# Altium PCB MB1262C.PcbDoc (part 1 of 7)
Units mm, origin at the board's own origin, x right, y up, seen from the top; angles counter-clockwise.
Board outline 208 x 250 mm, 6 copper layers (Top Layer, Layer 2, Layer 3, Layer 4, Layer 5, Bottom Layer), stack 1.596 mm thick; 483 components, 502 nets, 2134 pads, 1709 vias.
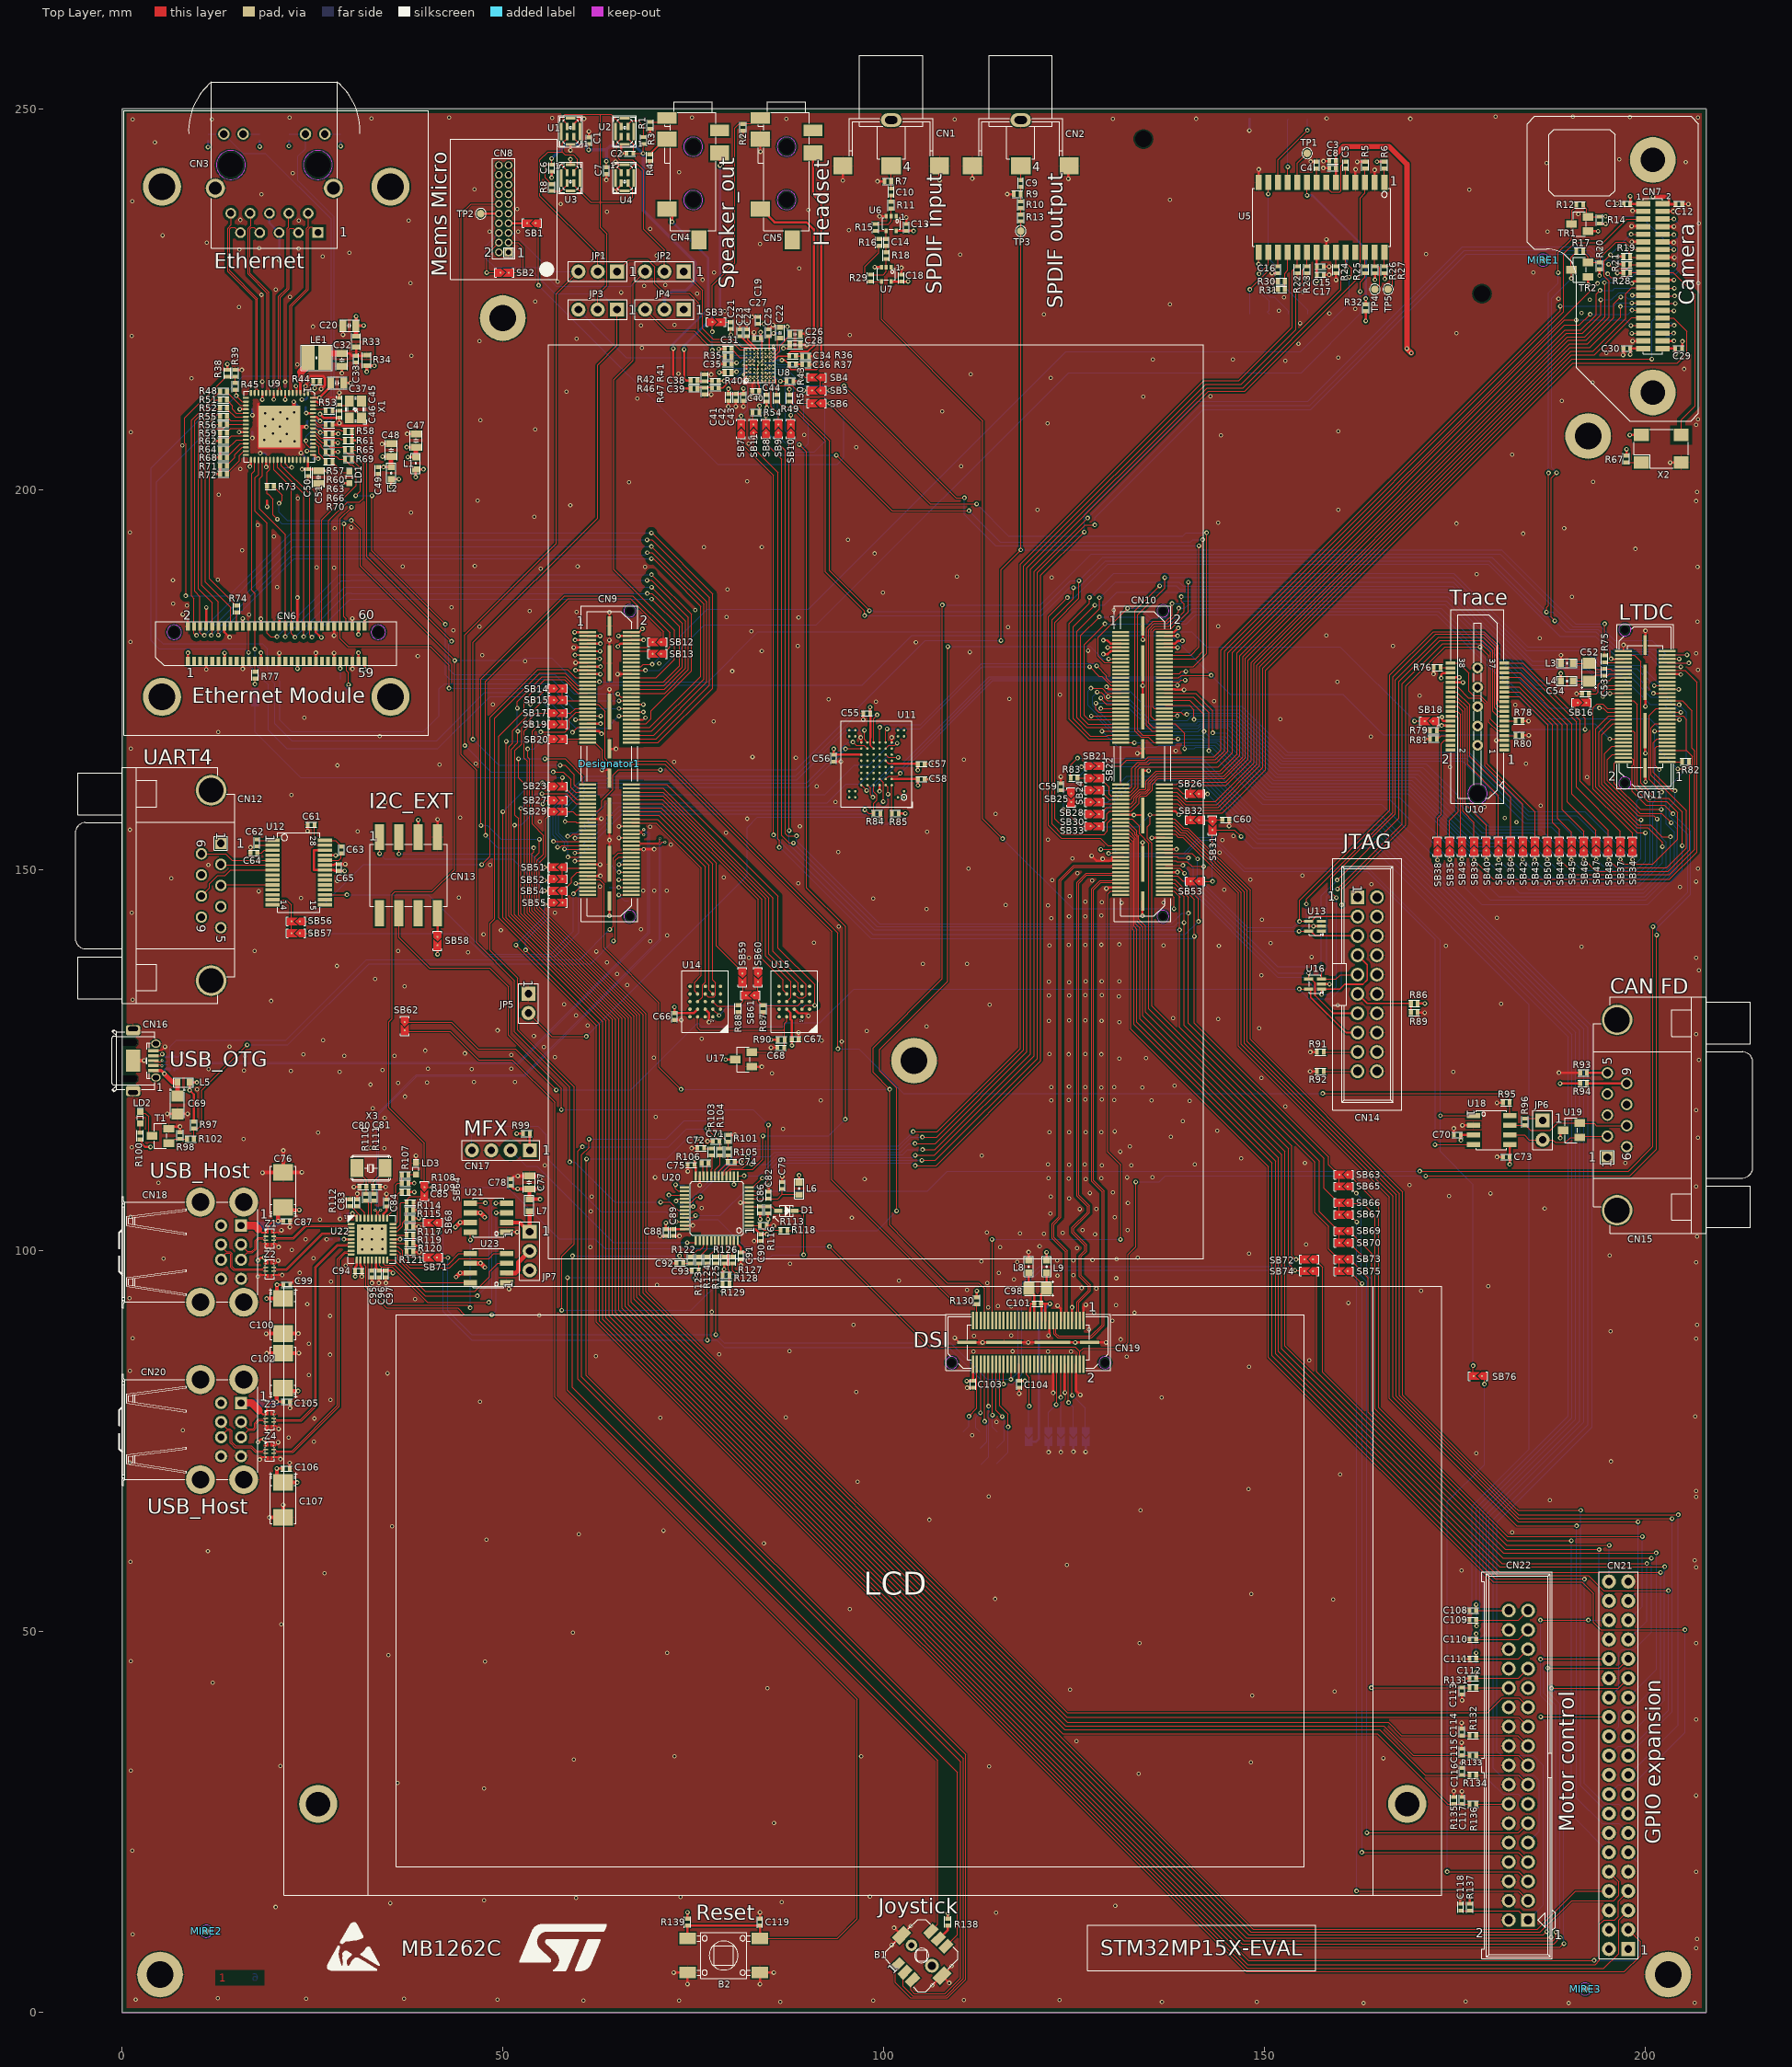
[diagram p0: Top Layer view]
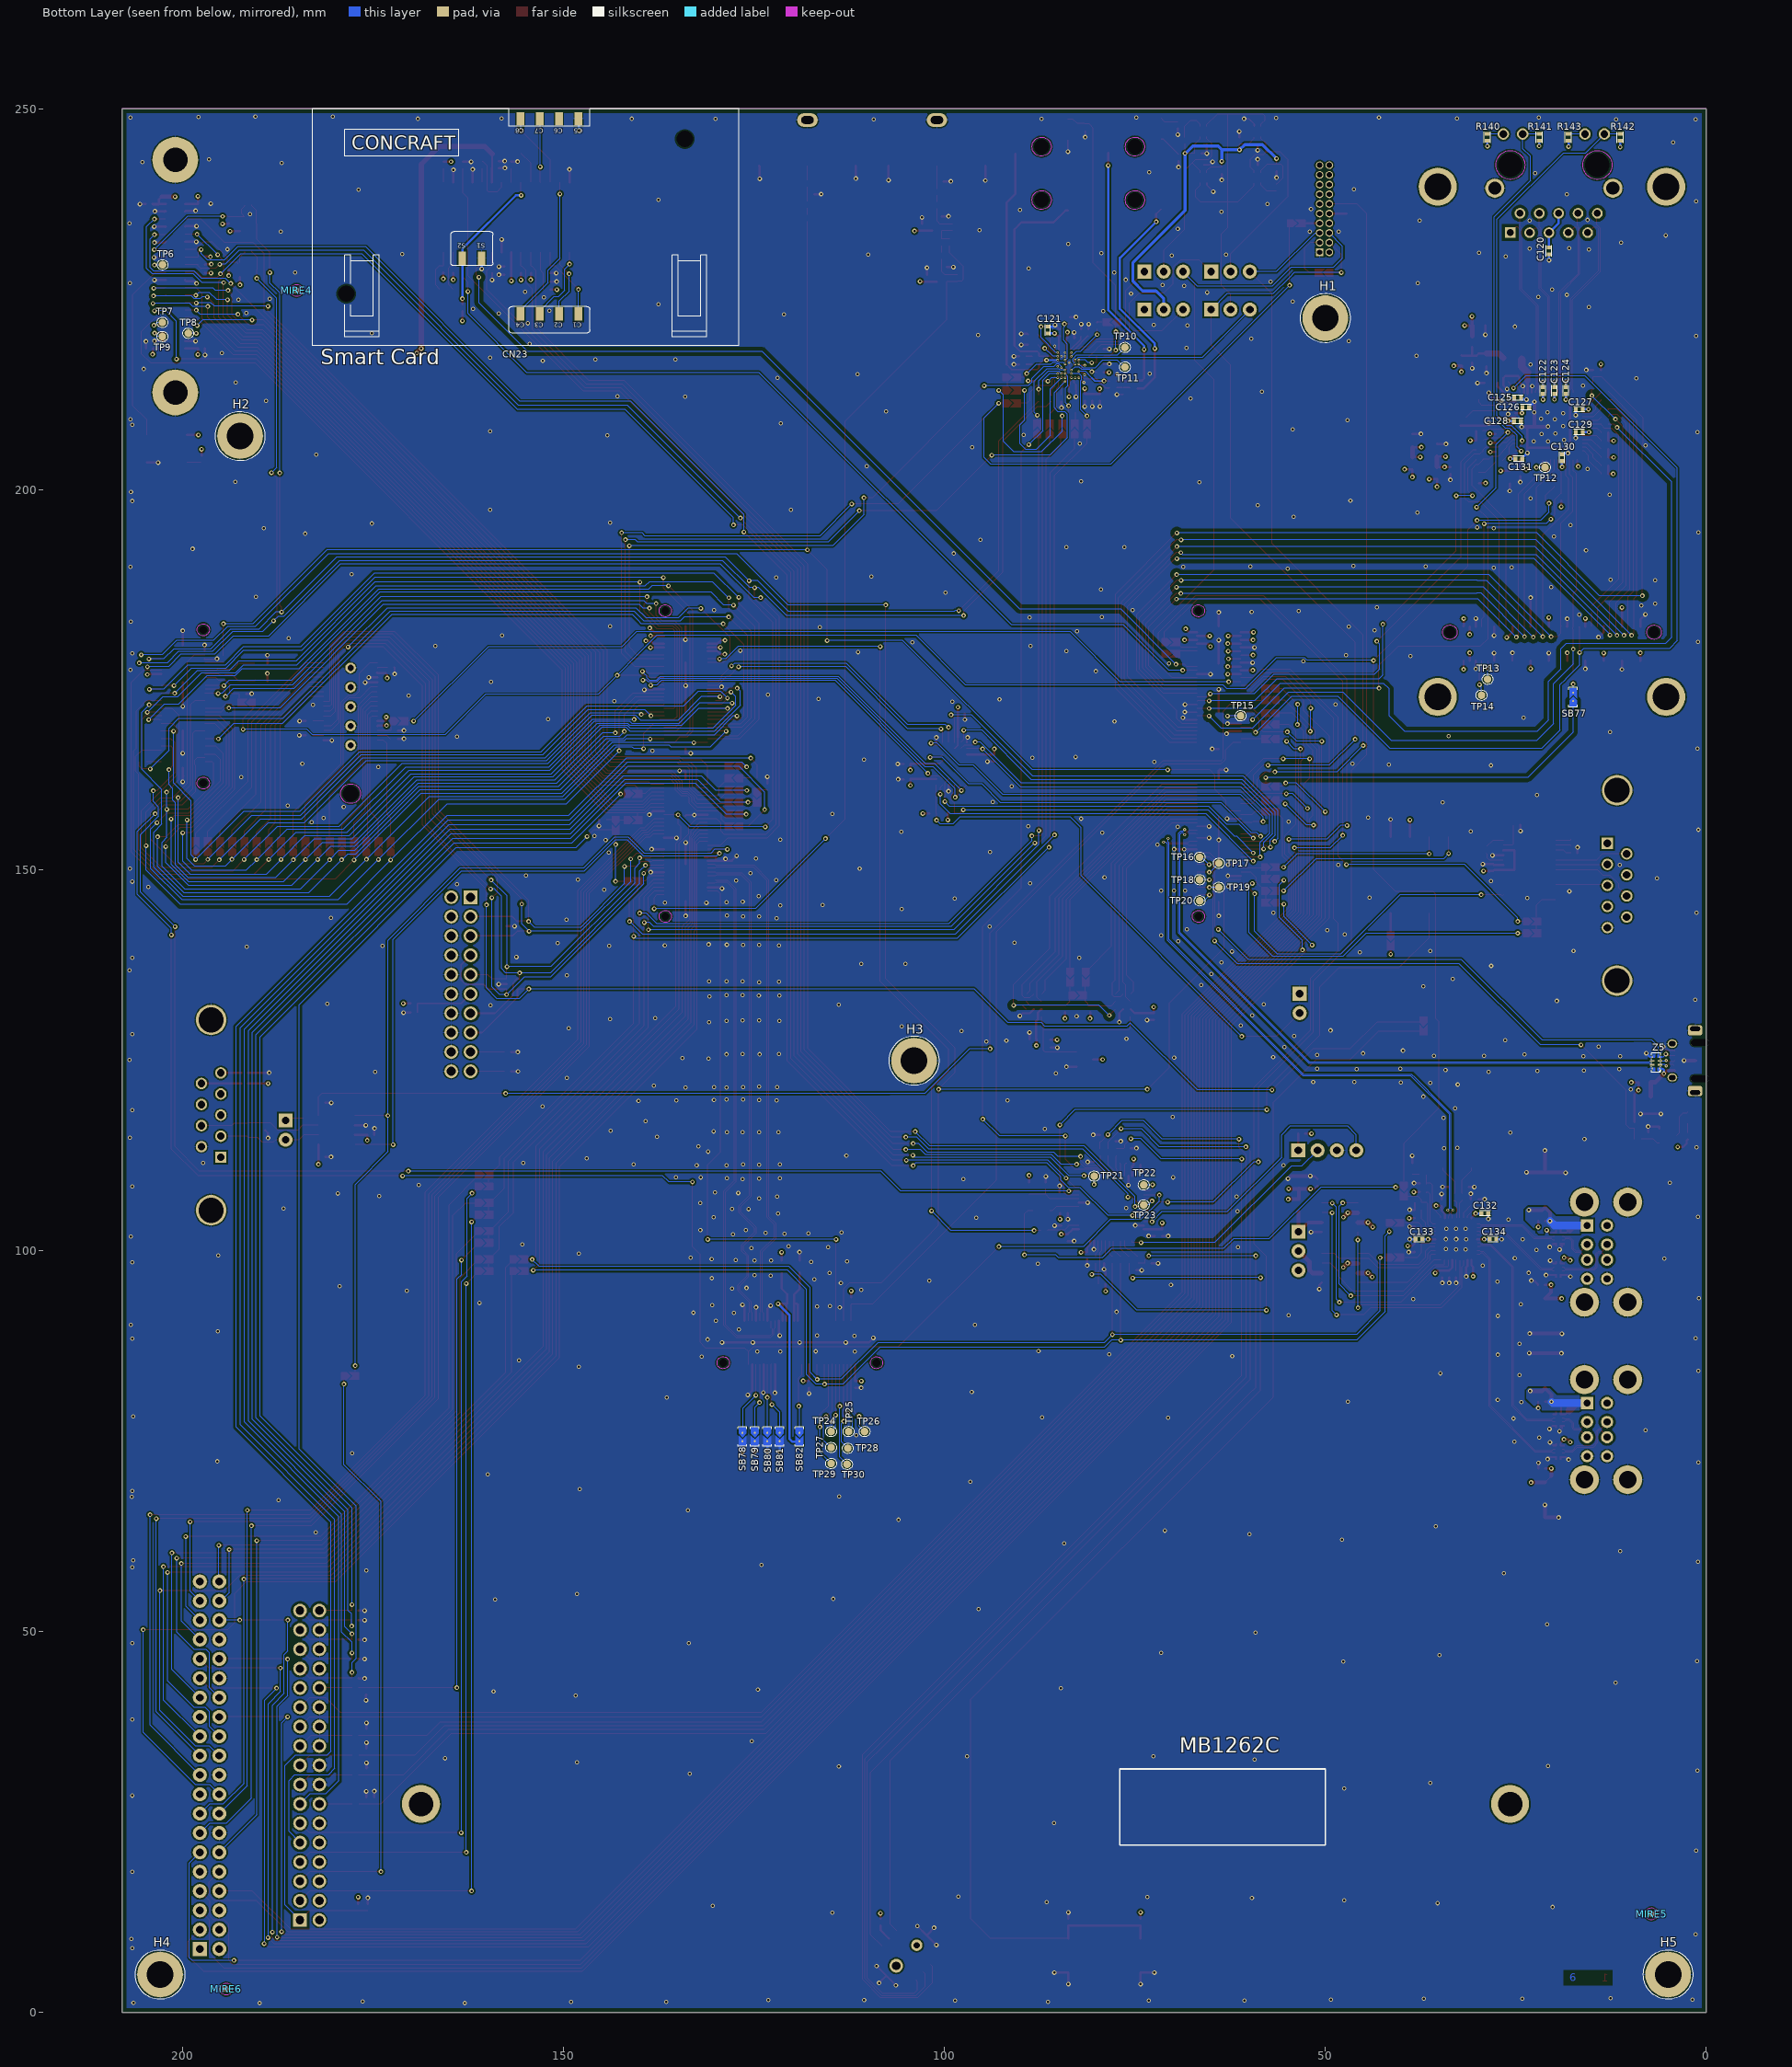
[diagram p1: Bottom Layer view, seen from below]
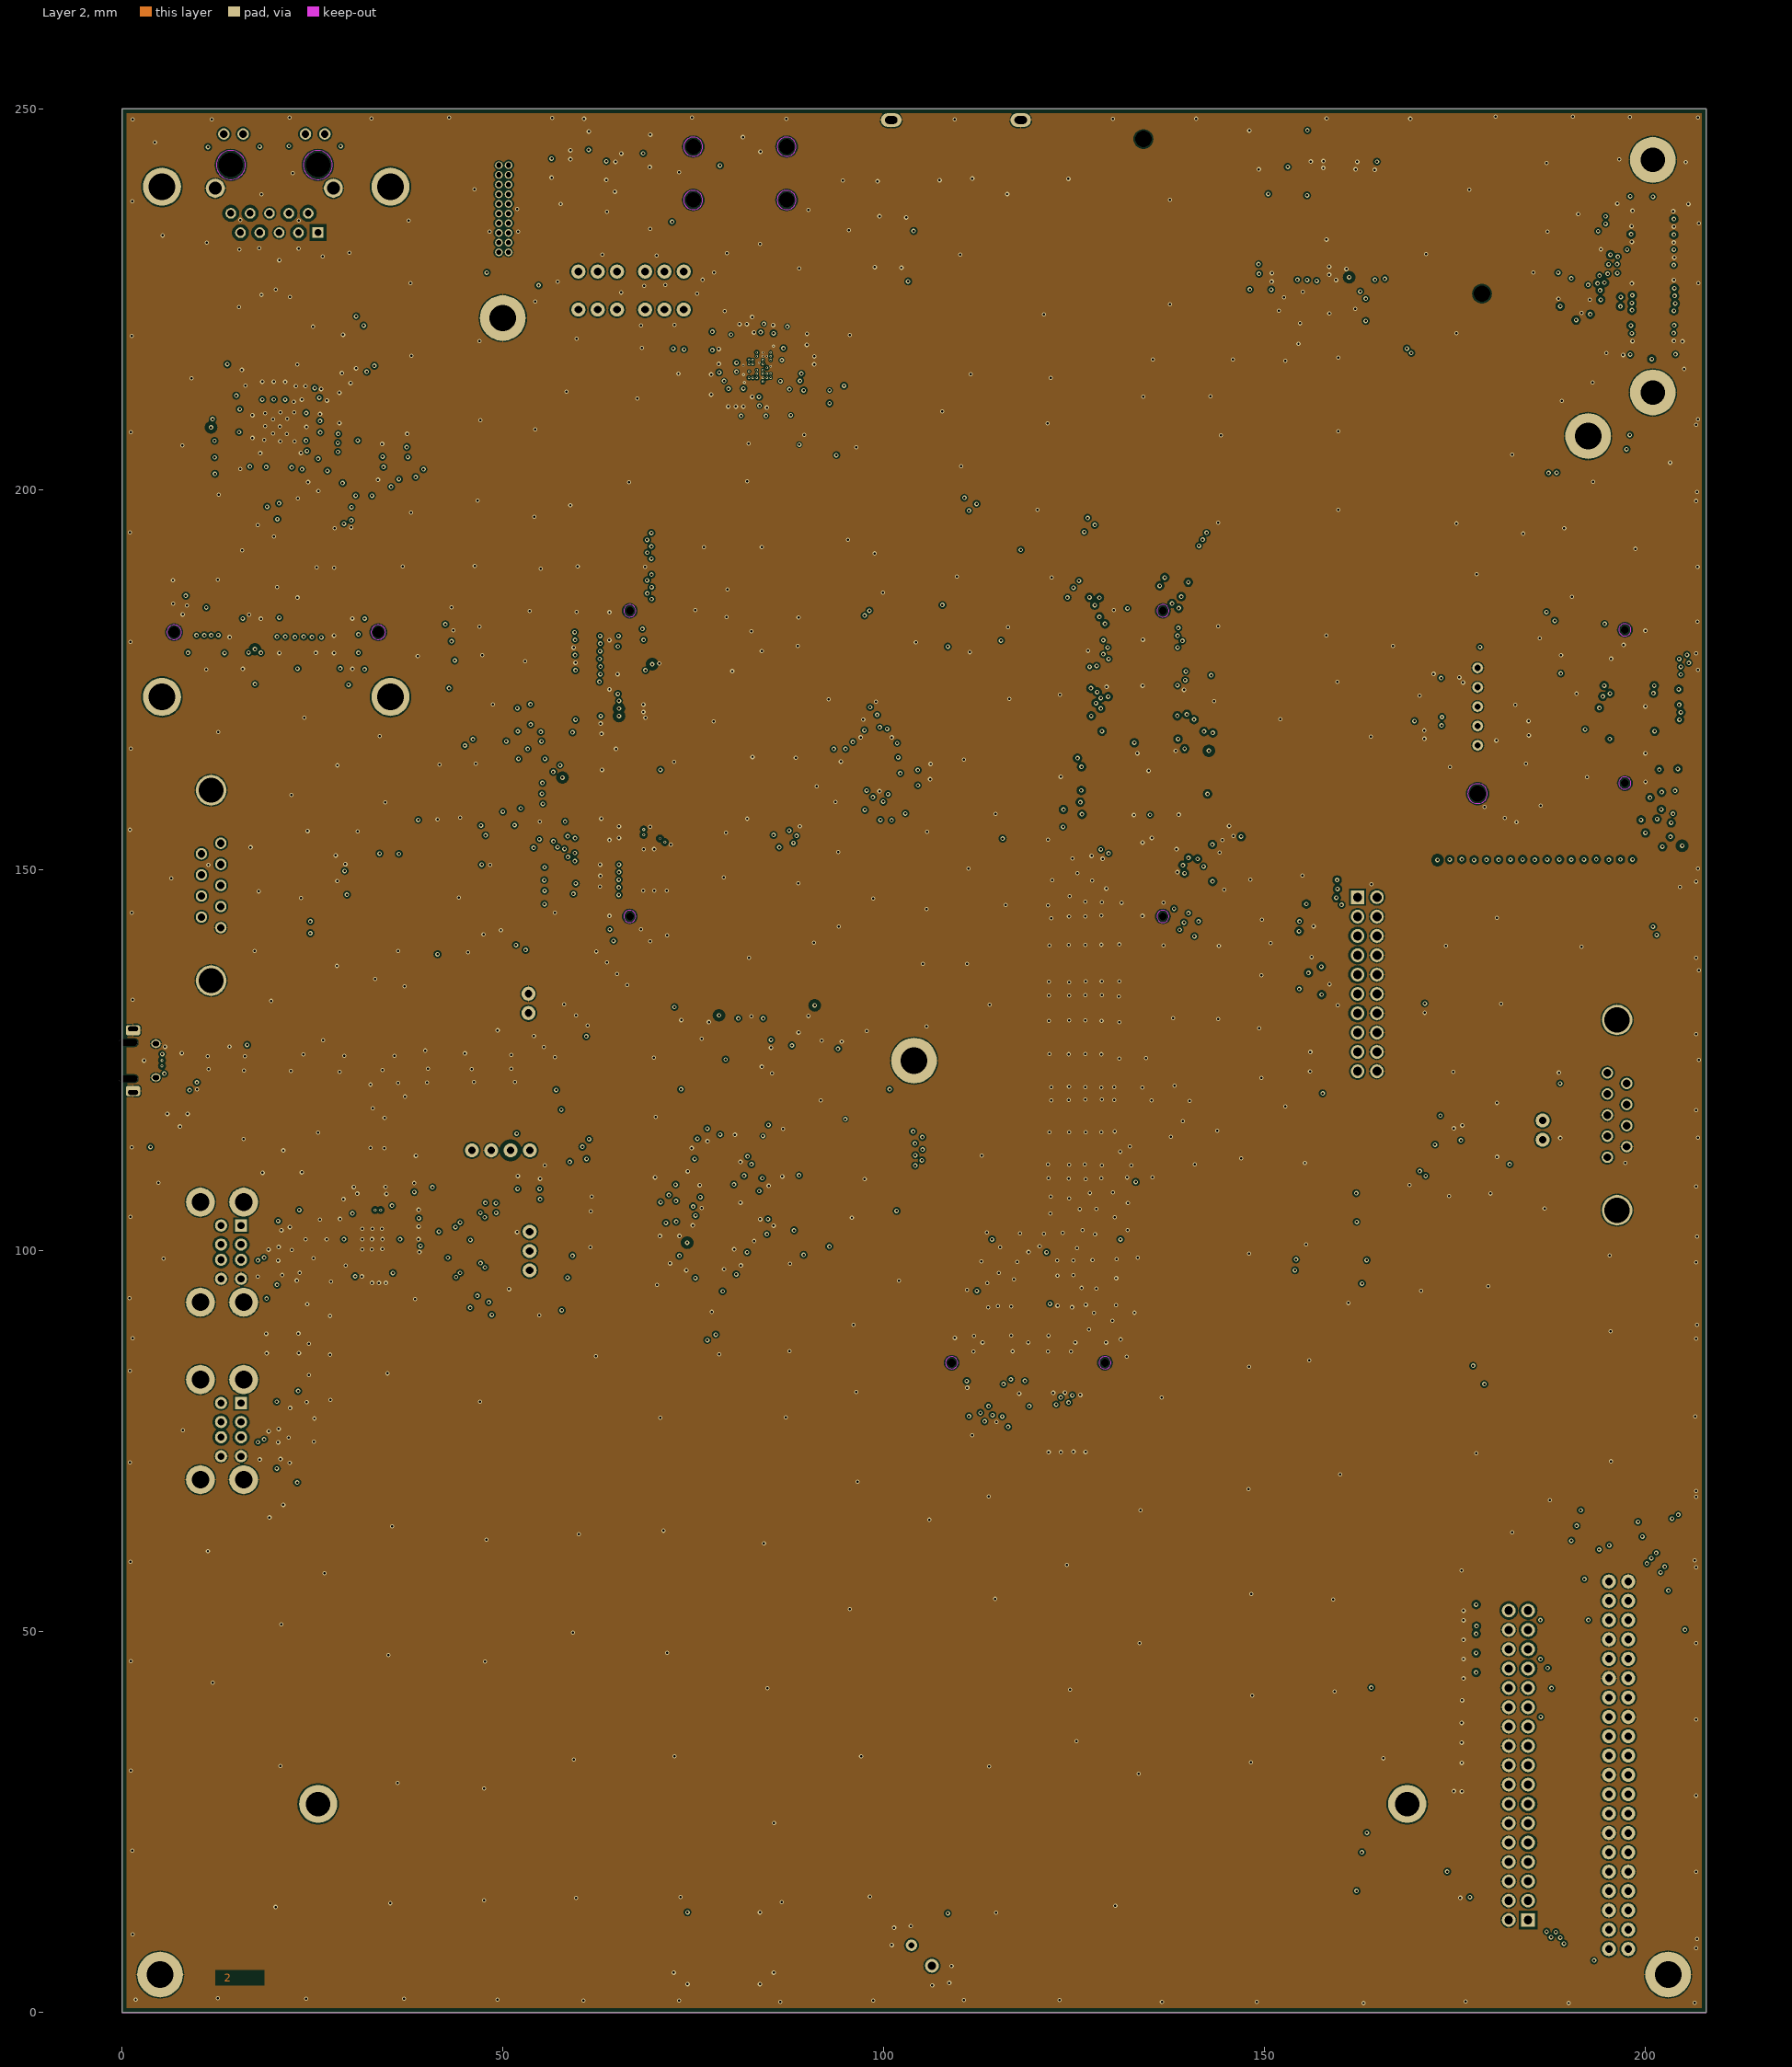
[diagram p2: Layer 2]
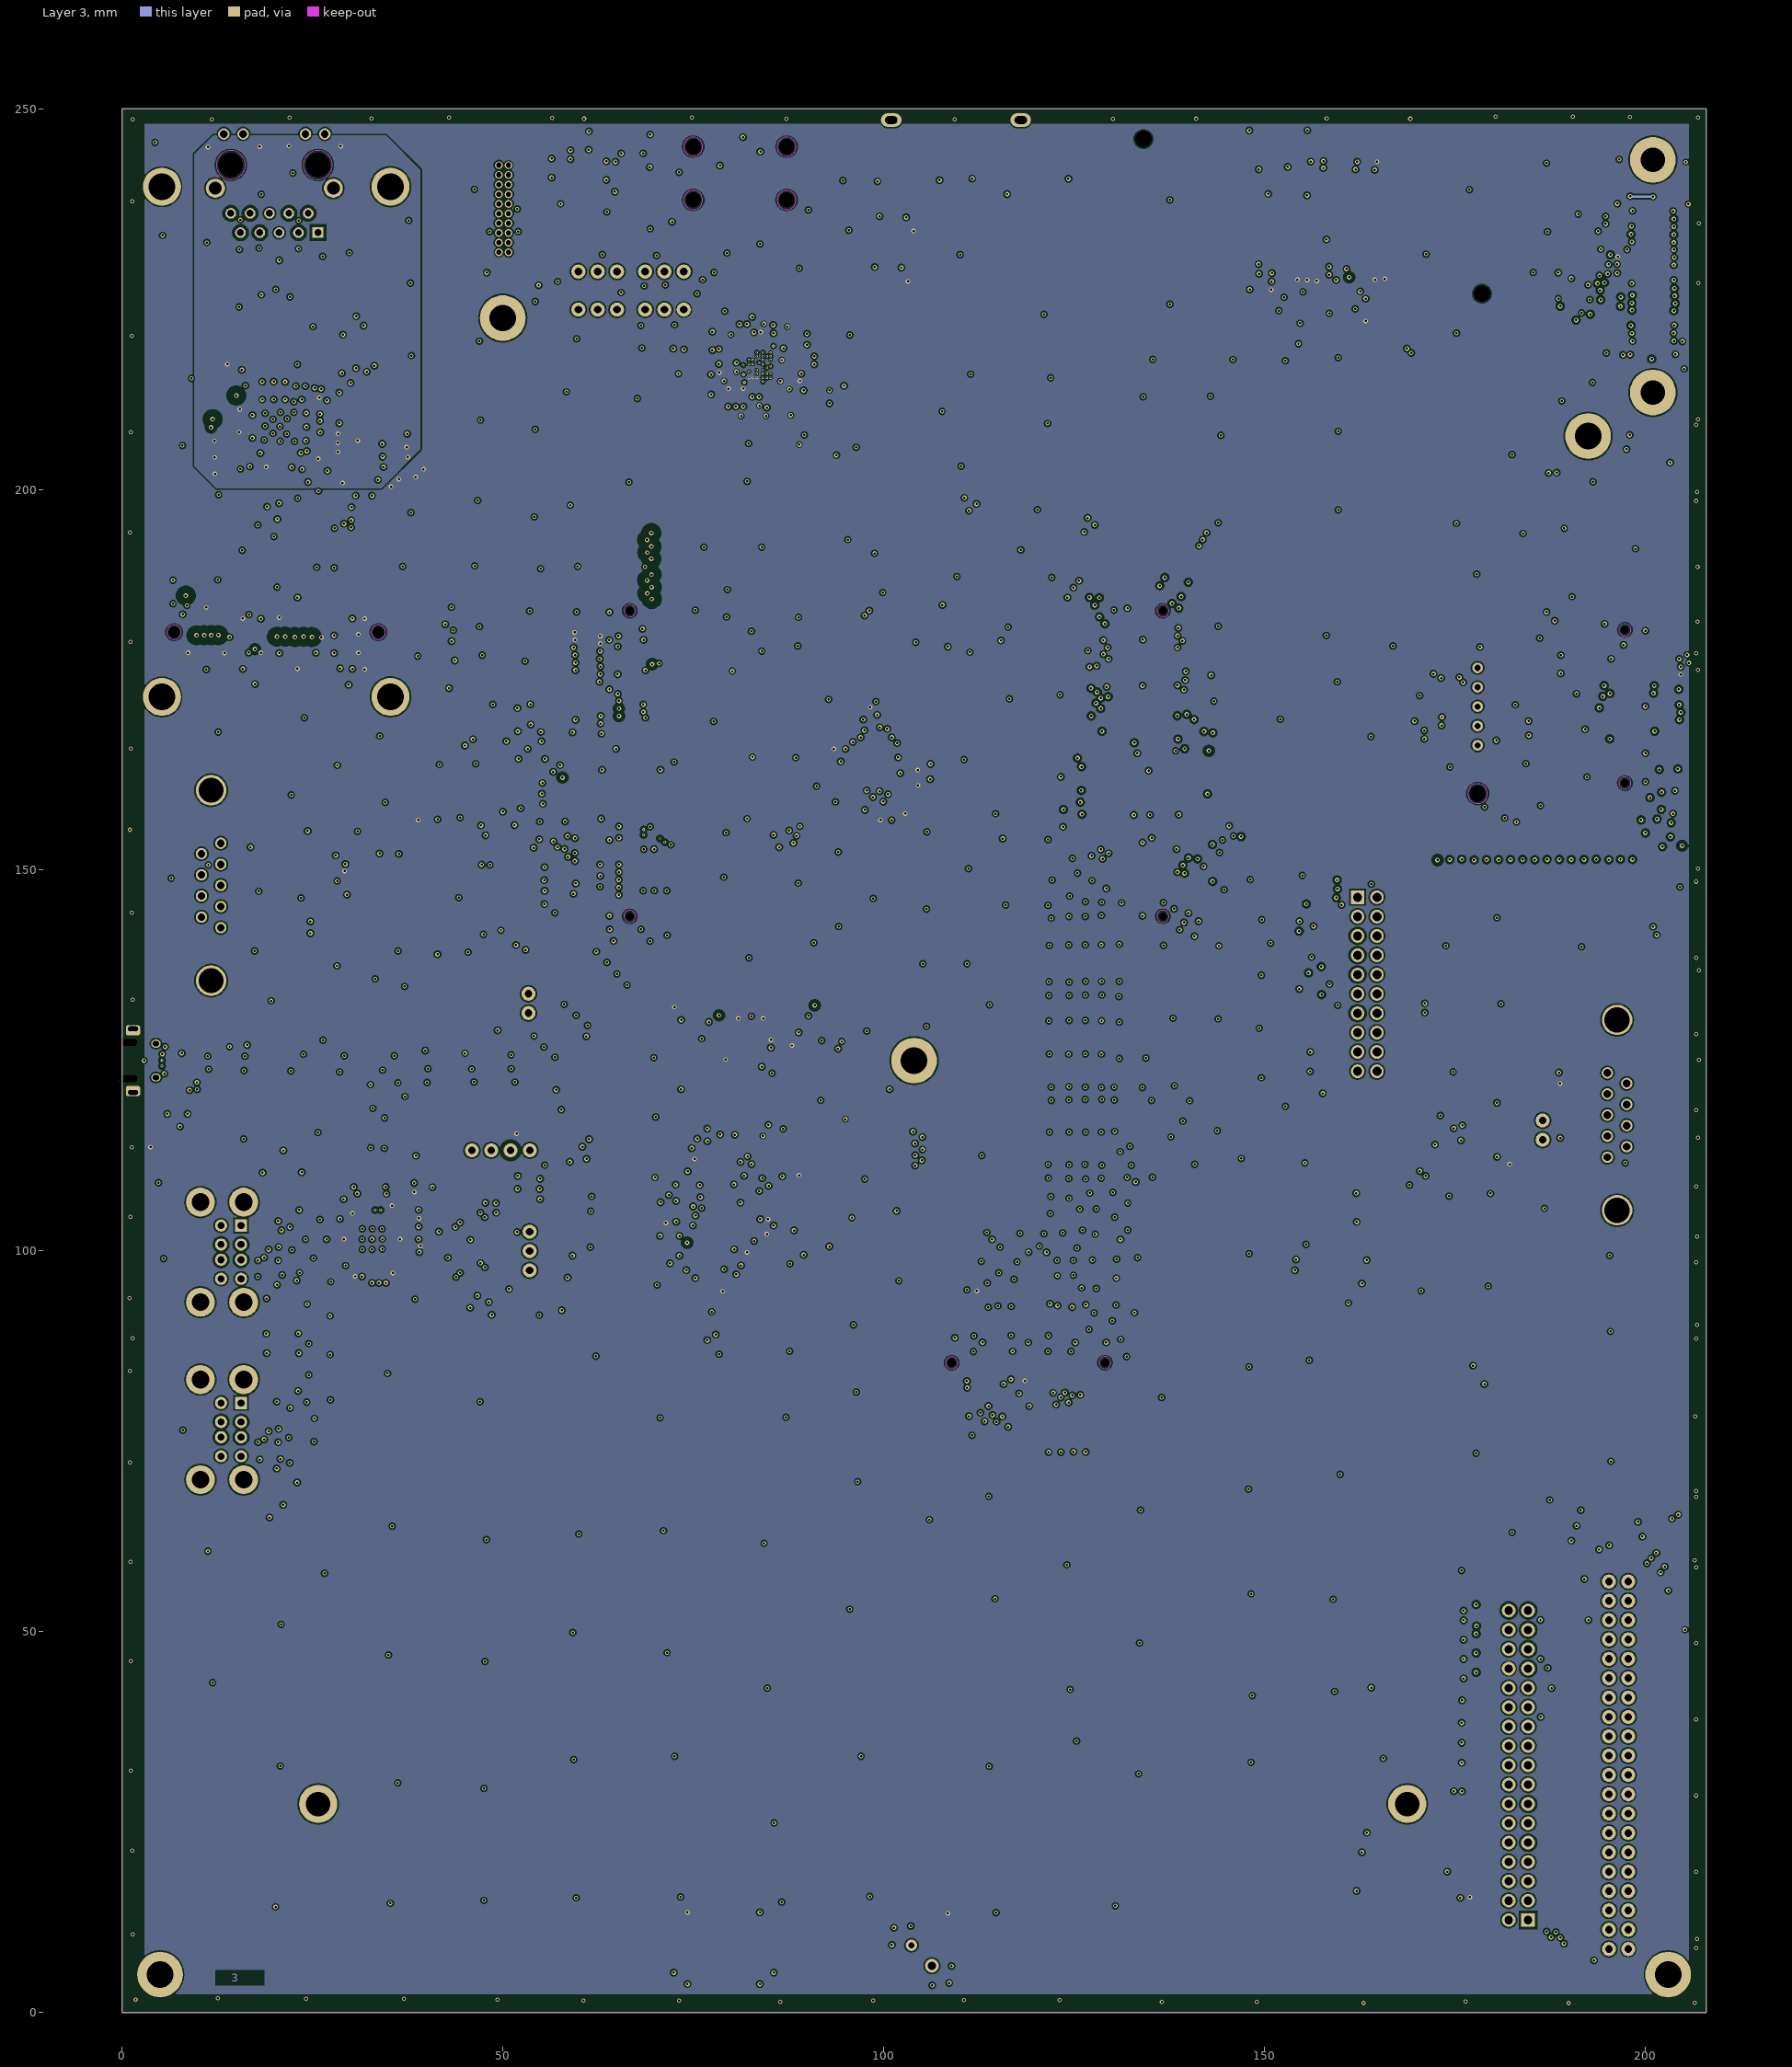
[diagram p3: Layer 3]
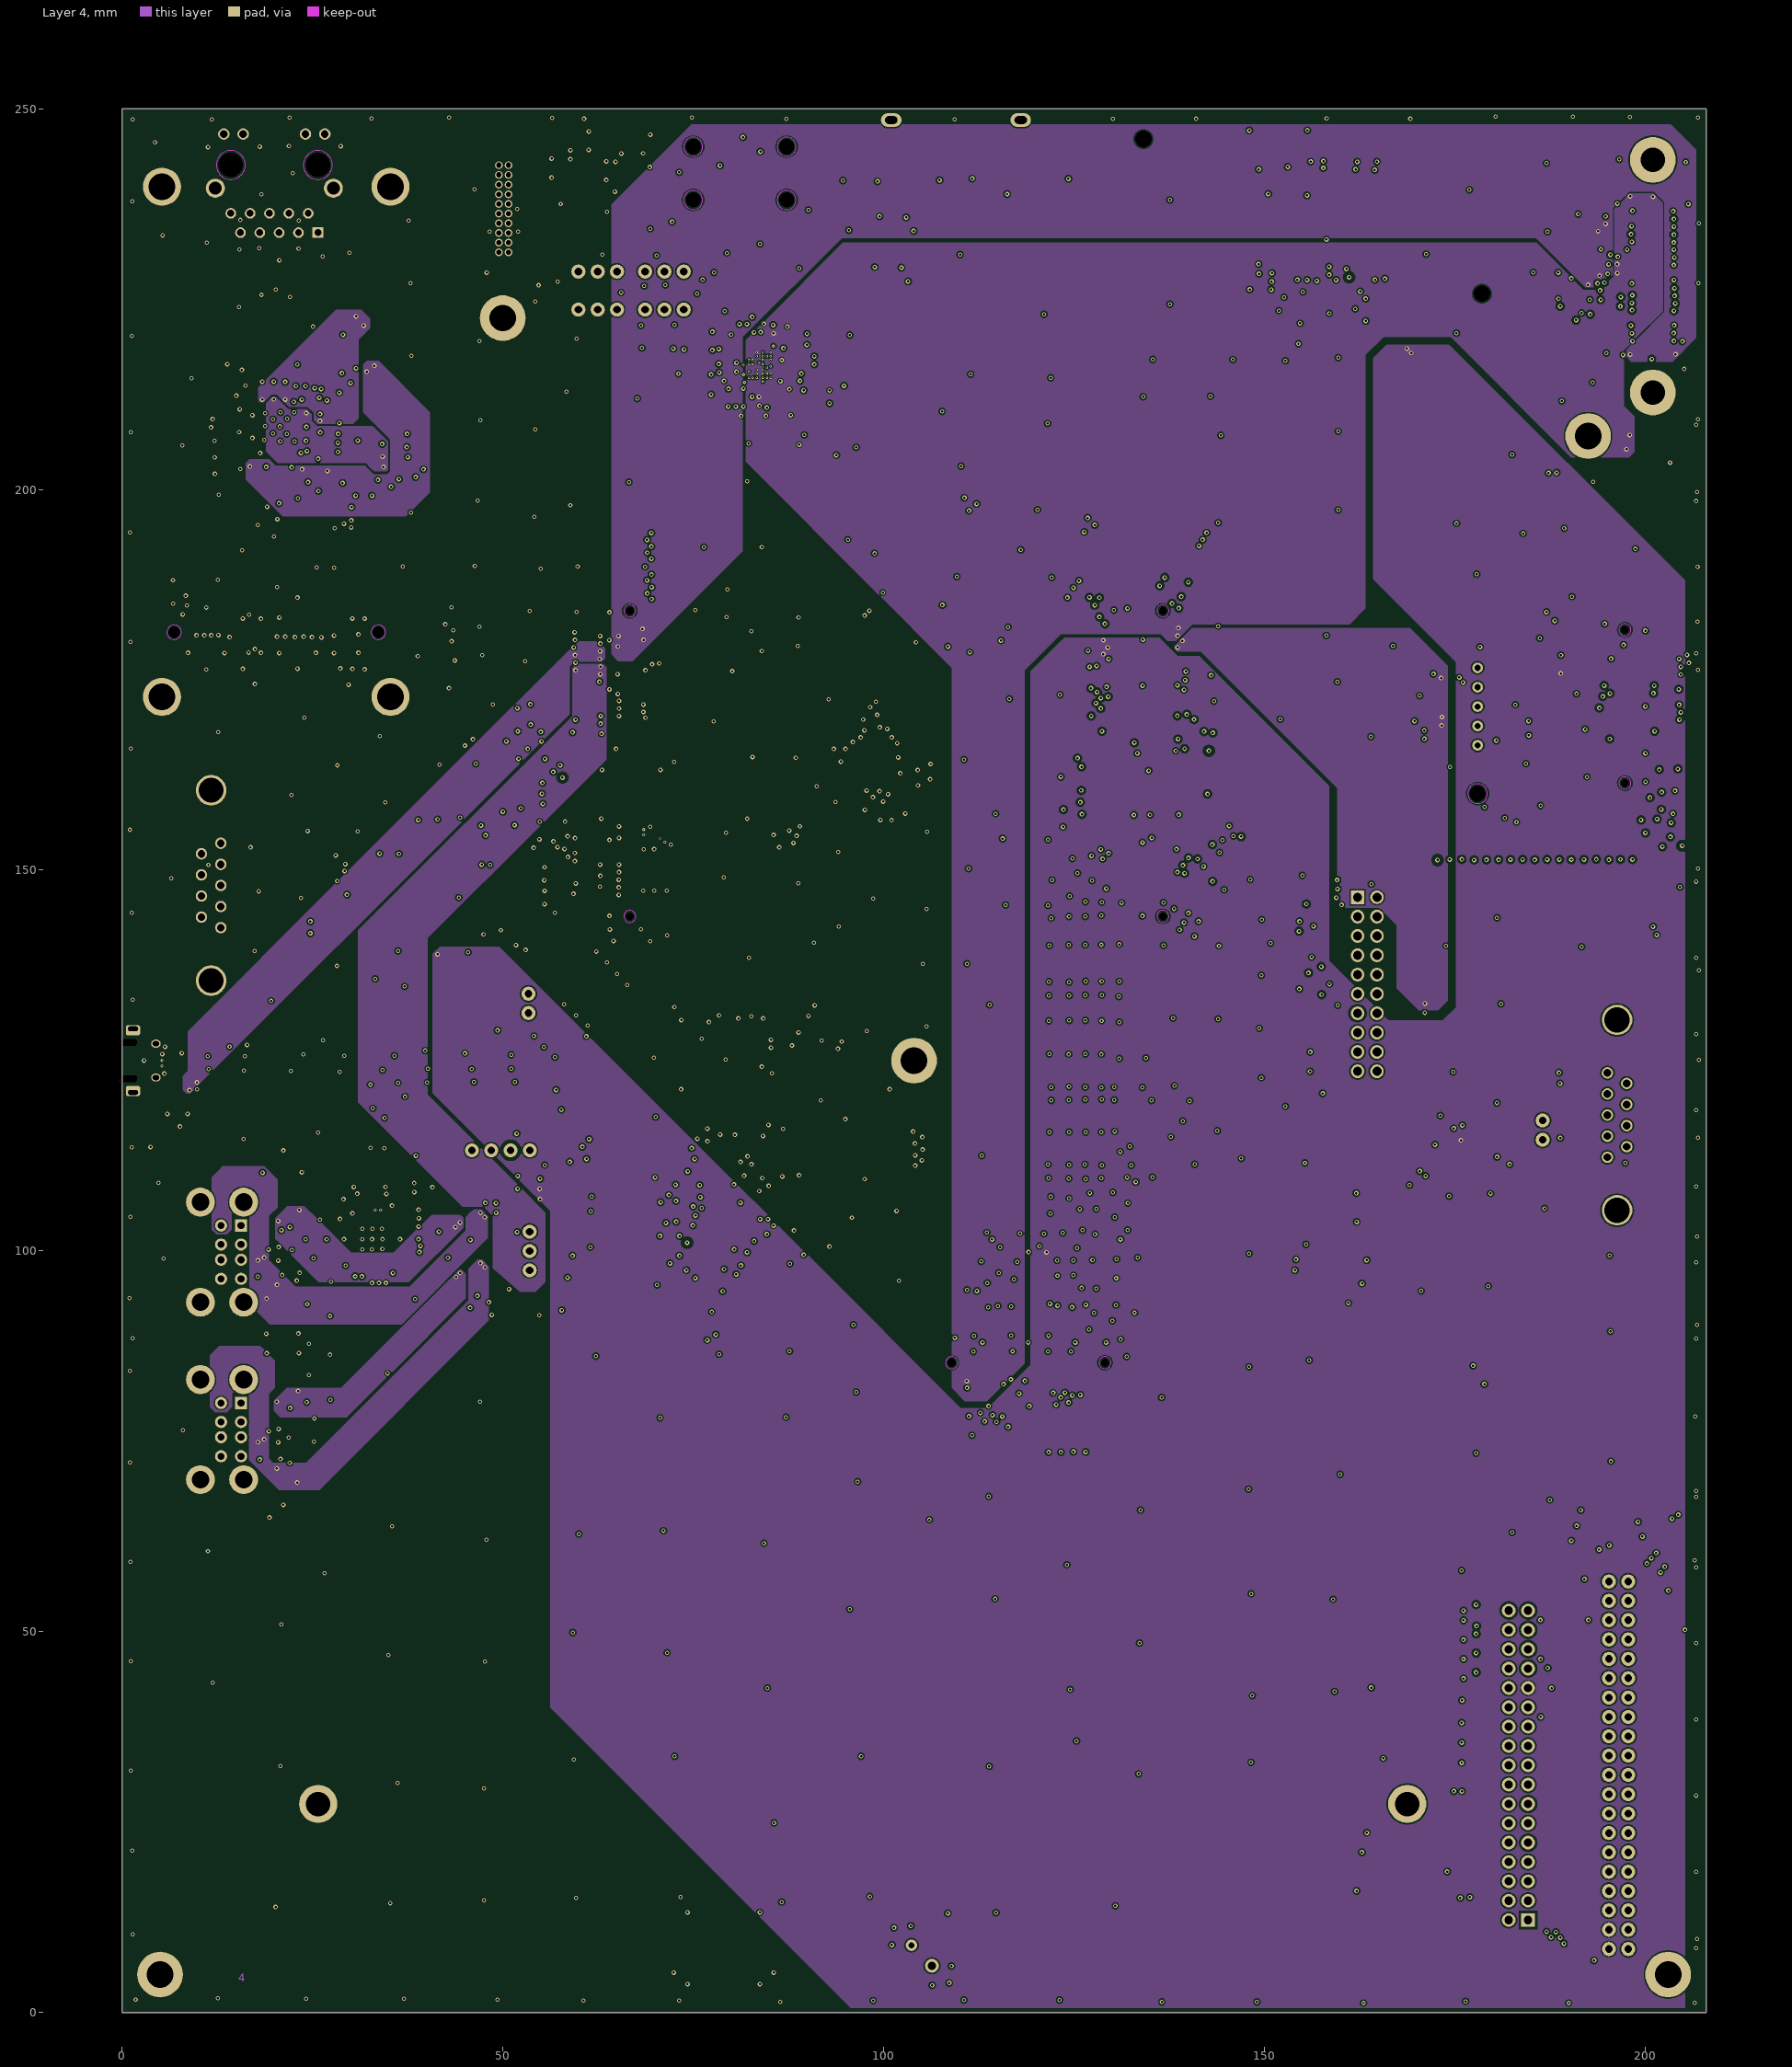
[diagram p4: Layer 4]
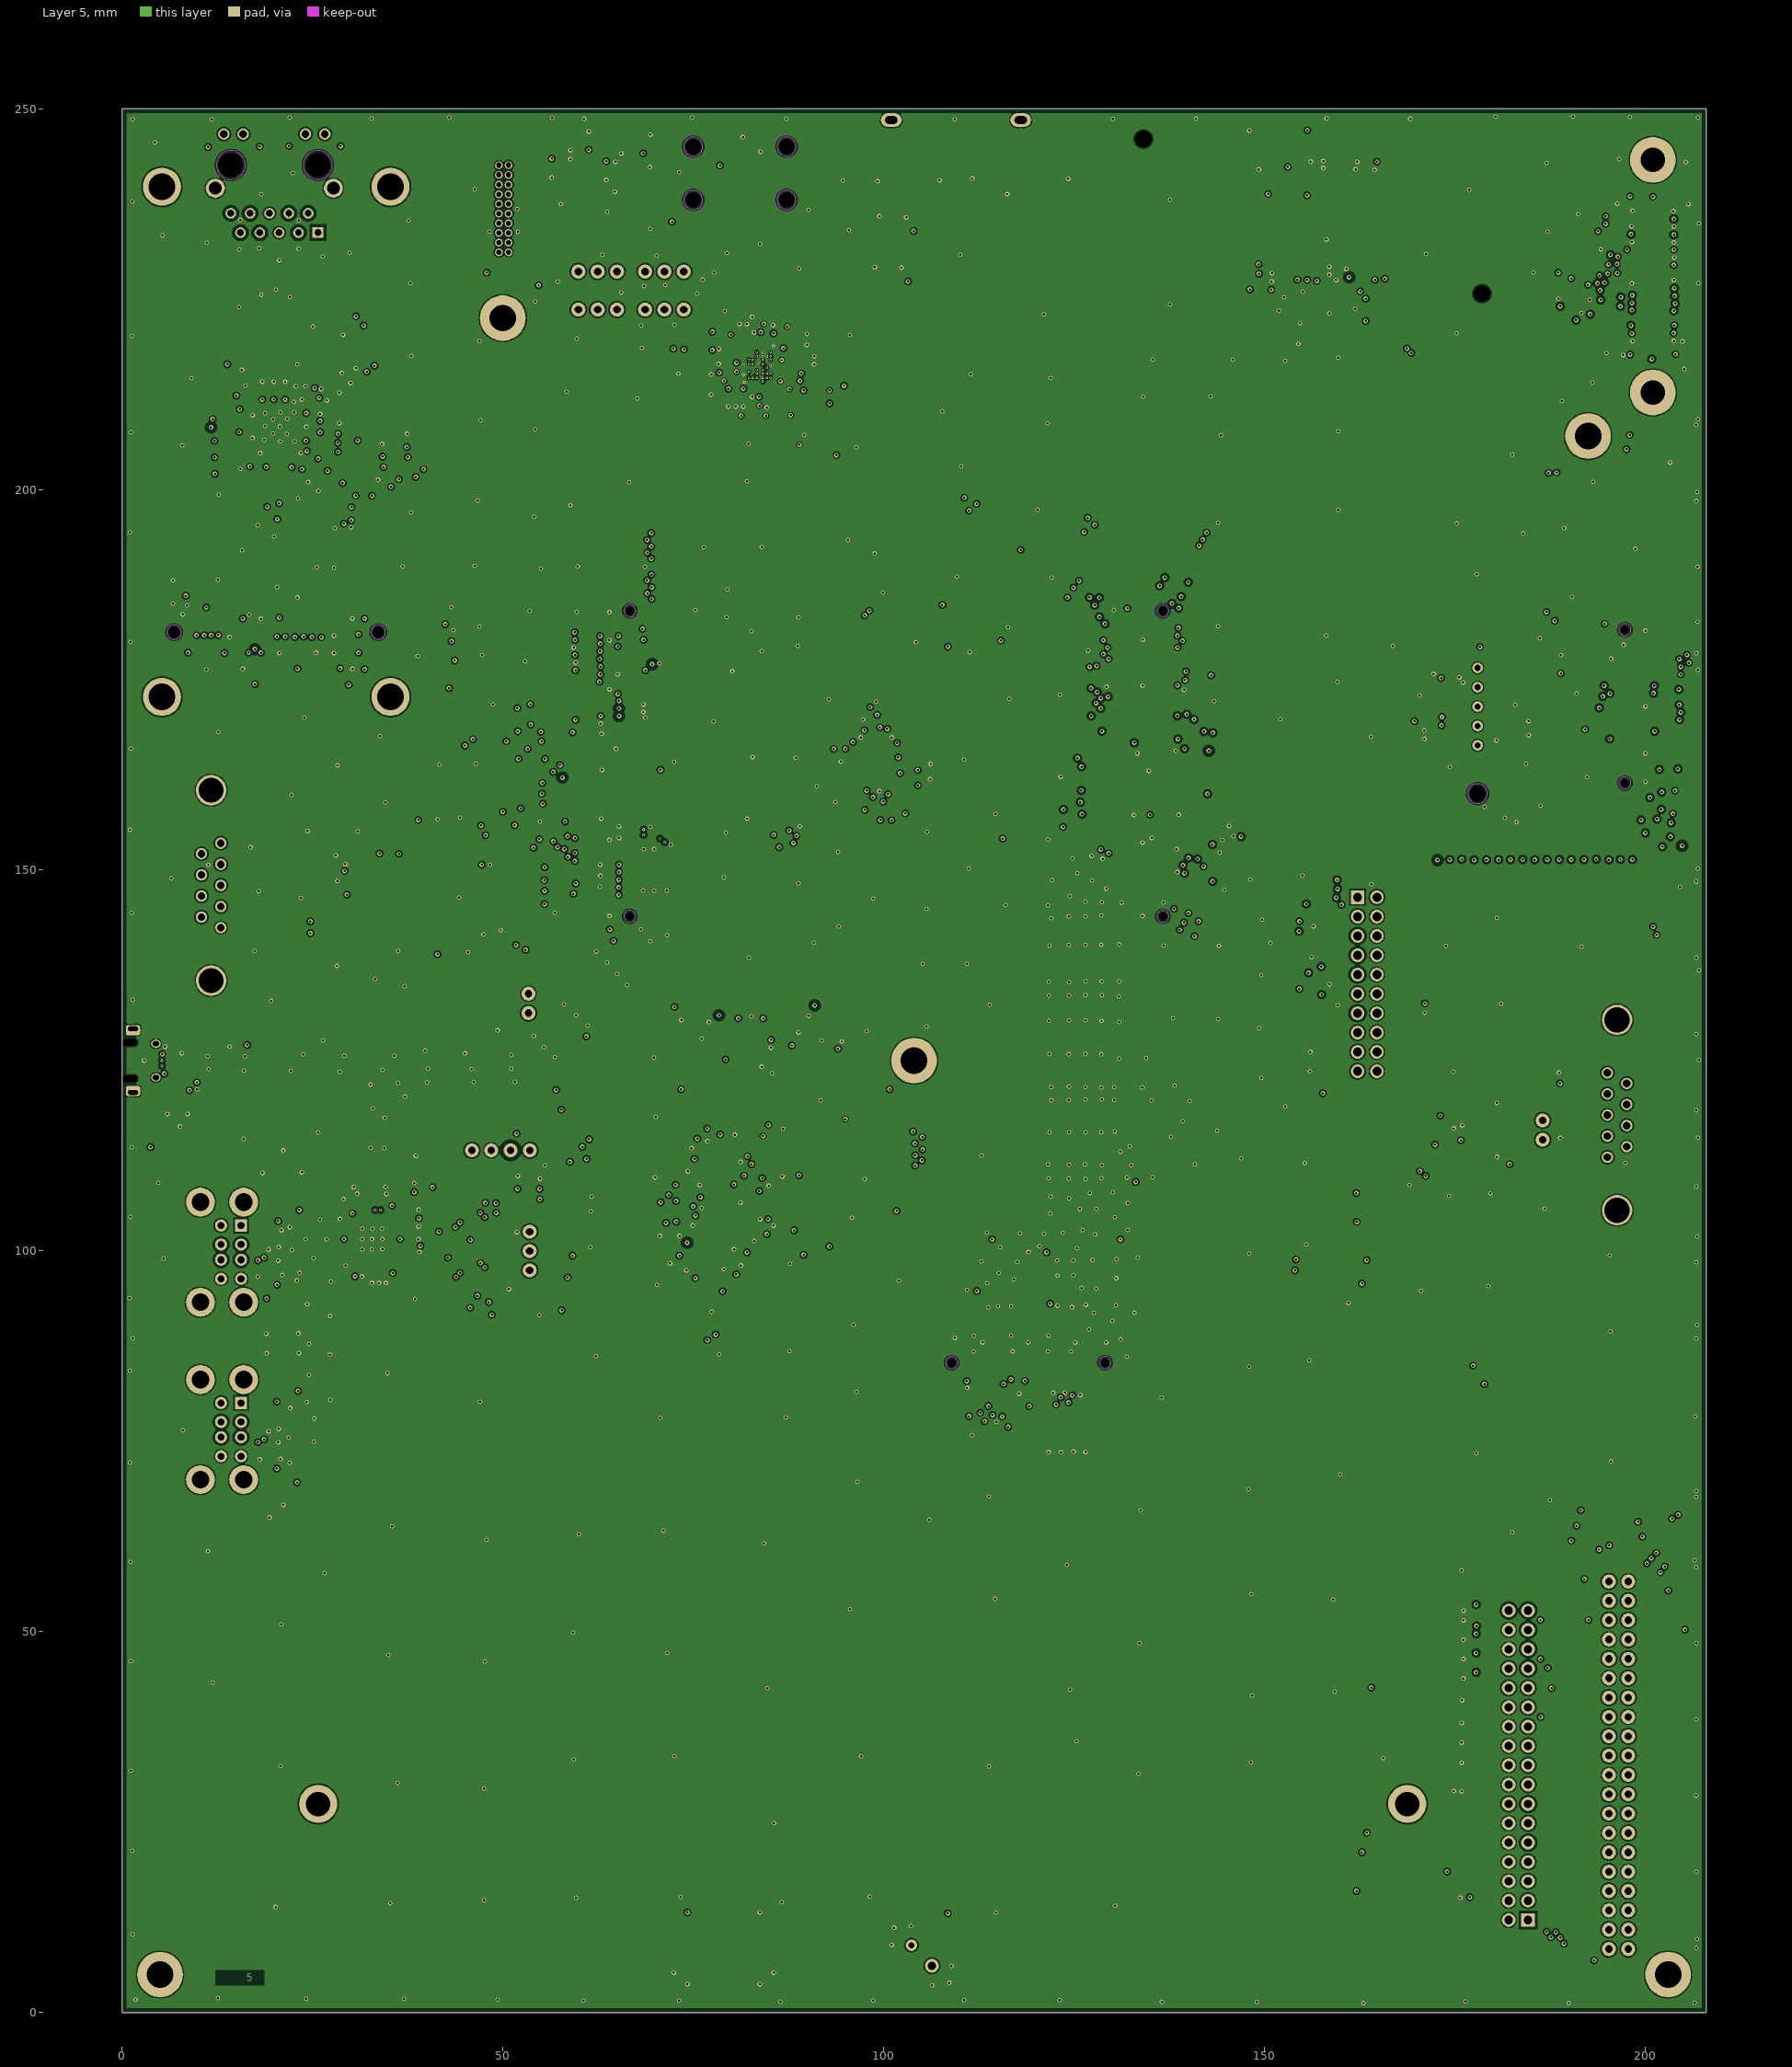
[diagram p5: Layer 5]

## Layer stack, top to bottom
Top Solder: solder mask 0.01, Solder Resist, Dk 3.5
Top Layer: signal copper 0.042
Dielectric 1: prepreg 0.093, FR4, Dk 4.2
Layer 2: signal copper 0.035
Dielectric 2: prepreg 0.1, FR4, Dk 4.2
Layer 3: signal copper 0.035
Dielectric 3: core 0.986, FR4, Dk 4.2
Layer 4: signal copper 0.035
Dielectric 4: prepreg 0.1, FR4, Dk 4.2
Layer 5: signal copper 0.035
Dielectric 5: prepreg 0.093, FR4, Dk 4.2
Bottom Layer: signal copper 0.042
Bottom Solder: solder mask 0.01, Solder Resist, Dk 3.5

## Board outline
0,250 0,0 208,0 208,250

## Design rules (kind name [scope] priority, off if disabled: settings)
BoardOutlineClearance [All] p1: gap=0.6 ignorepadtopadclearanceinfootprint=FALSE
Clearance CLEAR_50R_RGMII_ETH-TX_L1 [InNetClass('NET-CLASS_50R_RGMII_ETH-TX') vs OnLayer('Top Layer')] p1: gap=0.1 ignorepadtopadclearanceinfootprint=FALSE except(0: Arc-Hole Track-Hole SMDPad-Hole THPad-Hole Via-Hole Fill-Hole Poly-Hole Region-Hole Text-Hole; 0.2: Arc-THPad Track-THPad SMDPad-SMDPad SMDPad-THPad THPad-THPad; 0.26: Track-Track; 0.3: Via-Via Poly-Region Poly-Text; 0.52: Arc-Fill Arc-Poly Track-Fill Track-Poly SMDPad-Fill SMDPad-Poly THPad-Fill THPad-Poly Via-Fill Via-Poly Fill-Fill Fill-Poly Poly-Poly)
Clearance CLEAR_50R_RGMII_ETH-TX_L6 [InNetClass('NET-CLASS_50R_RGMII_ETH-TX') vs OnLayer('Bottom Layer')] p2: gap=0.1 ignorepadtopadclearanceinfootprint=FALSE except(0: Arc-Hole Track-Hole SMDPad-Hole THPad-Hole Via-Hole Fill-Hole Poly-Hole Region-Hole Text-Hole; 0.2: Arc-THPad Track-THPad SMDPad-SMDPad SMDPad-THPad THPad-THPad; 0.26: Track-Track; 0.3: Via-Via Poly-Region Poly-Text; 0.52: Arc-Fill Arc-Poly Track-Fill Track-Poly SMDPad-Fill SMDPad-Poly THPad-Fill THPad-Poly Via-Fill Via-Poly Fill-Fill Fill-Poly Poly-Poly)
Clearance CLEAR_50R_RGMII_ETH-TX_L3 [OnLayer('Layer 3') vs InNetClass('NET-CLASS_50R_RGMII_ETH-TX')] p3: gap=0.1 ignorepadtopadclearanceinfootprint=FALSE except(0: Arc-Hole Track-Hole SMDPad-Hole THPad-Hole Via-Hole Fill-Hole Poly-Hole Region-Hole Text-Hole; 0.2: Arc-THPad Track-THPad SMDPad-SMDPad SMDPad-THPad THPad-THPad; 0.3: Via-Via Poly-Region Poly-Text; 0.5: Track-Track; 1: Arc-Fill Arc-Poly Track-Fill Track-Poly SMDPad-Fill SMDPad-Poly THPad-Fill THPad-Poly Via-Fill Via-Poly Fill-Fill Fill-Poly Poly-Poly)
Clearance CLEAR_50R_RGMII_ETH-RX_L1 [InNetClass('NET-CLASS_50R_RGMII_ETH-RX') vs OnLayer('Top Layer')] p4: gap=0.1 ignorepadtopadclearanceinfootprint=FALSE except(0: Arc-Hole Track-Hole SMDPad-Hole THPad-Hole Via-Hole Fill-Hole Poly-Hole Region-Hole Text-Hole; 0.2: Arc-THPad Track-THPad SMDPad-SMDPad SMDPad-THPad THPad-THPad; 0.26: Track-Track; 0.3: Via-Via Poly-Region Poly-Text; 0.52: Arc-Fill Arc-Poly Track-Fill Track-Poly SMDPad-Fill SMDPad-Poly THPad-Fill THPad-Poly Via-Fill Via-Poly Fill-Fill Fill-Poly Poly-Poly)
Clearance CLEAR_50R_RGMII_ETH-RX_L6 [OnLayer('Bottom Layer') vs InNetClass('NET-CLASS_50R_RGMII_ETH-RX')] p5: gap=0.1 ignorepadtopadclearanceinfootprint=FALSE except(0: Arc-Hole Track-Hole SMDPad-Hole THPad-Hole Via-Hole Fill-Hole Poly-Hole Region-Hole Text-Hole; 0.2: Arc-THPad Track-THPad SMDPad-SMDPad SMDPad-THPad THPad-THPad; 0.26: Track-Track; 0.3: Via-Via Poly-Region Poly-Text; 0.52: Arc-Fill Arc-Poly Track-Fill Track-Poly SMDPad-Fill SMDPad-Poly THPad-Fill THPad-Poly Via-Fill Via-Poly Fill-Fill Fill-Poly Poly-Poly)
Clearance CLEAR_50R_RGMII_ETH-RX_L3 [OnLayer('Layer 3') vs InNetClass('NET-CLASS_50R_RGMII_ETH-RX')] p6: gap=0.1 ignorepadtopadclearanceinfootprint=FALSE except(0: Arc-Hole Track-Hole SMDPad-Hole THPad-Hole Via-Hole Fill-Hole Poly-Hole Region-Hole Text-Hole; 0.2: Arc-THPad Track-THPad SMDPad-SMDPad SMDPad-THPad THPad-THPad; 0.3: Via-Via Poly-Region Poly-Text; 0.5: Track-Track; 1: Arc-Fill Arc-Poly Track-Fill Track-Poly SMDPad-Fill SMDPad-Poly THPad-Fill THPad-Poly Via-Fill Via-Poly Fill-Fill Fill-Poly Poly-Poly)
Clearance CLEAR_50R_TRACE-RGB_TRACED-LTDC [InNetClass('NET-CLASS_50R_TRACE-RGB_TRACED-LTDC')] p7: gap=0.1 ignorepadtopadclearanceinfootprint=FALSE except(0: Arc-Hole Track-Hole SMDPad-Hole THPad-Hole Via-Hole Fill-Hole Poly-Hole Region-Hole Text-Hole; 0.2: Arc-THPad Track-THPad SMDPad-SMDPad SMDPad-THPad THPad-THPad; 0.3: Arc-Fill Arc-Poly Track-Fill Track-Poly SMDPad-Fill SMDPad-Poly THPad-Fill THPad-Poly Via-Via Via-Fill Via-Poly Fill-Fill Fill-Poly Poly-Poly Poly-Region Poly-Text)
Clearance CLEAR_50R_JTAG_JT [InNetClass('NET-CLASS_50R_JTAG_JT')] p8: gap=0.1 ignorepadtopadclearanceinfootprint=FALSE except(0: Arc-Hole Track-Hole SMDPad-Hole THPad-Hole Via-Hole Fill-Hole Poly-Hole Region-Hole Text-Hole; 0.2: Arc-THPad Track-THPad SMDPad-SMDPad SMDPad-THPad THPad-THPad; 0.3: Arc-Fill Arc-Poly Track-Fill Track-Poly SMDPad-Fill SMDPad-Poly THPad-Fill THPad-Poly Via-Via Via-Fill Via-Poly Fill-Fill Fill-Poly Poly-Poly Poly-Region Poly-Text)
Clearance CLEAR_50R_DCMI [InNetClass('NET-CLASS_50R_DCMI')] p9: gap=0.1 ignorepadtopadclearanceinfootprint=FALSE except(0: Arc-Hole Track-Hole SMDPad-Hole THPad-Hole Via-Hole Fill-Hole Poly-Hole Region-Hole Text-Hole; 0.2: Arc-THPad Track-THPad SMDPad-SMDPad SMDPad-THPad THPad-THPad; 0.3: Arc-Fill Arc-Poly Track-Fill Track-Poly SMDPad-Fill SMDPad-Poly THPad-Fill THPad-Poly Via-Via Via-Fill Via-Poly Fill-Fill Fill-Poly Poly-Poly Poly-Region Poly-Text)
Clearance CLEAR_NAND_D [InNetClass('NET-CLASS_NAND_D')] p10: gap=0.1 ignorepadtopadclearanceinfootprint=FALSE except(0: Arc-Hole Track-Hole SMDPad-Hole THPad-Hole Via-Hole Fill-Hole Poly-Hole Region-Hole Text-Hole; 0.2: Arc-THPad Arc-Fill Arc-Poly Track-THPad Track-Fill Track-Poly SMDPad-SMDPad SMDPad-THPad SMDPad-Fill SMDPad-Poly THPad-THPad THPad-Fill THPad-Poly Via-Fill Via-Poly Fill-Fill Fill-Poly Poly-Poly Poly-Region Poly-Text; 0.3: Via-Via)
Clearance CLEAR_BGA050-AUDIO [InNetClass('NET-CLASS_BGA050-AUDIO_VIA')] p11: gap=0.1 ignorepadtopadclearanceinfootprint=FALSE except(0: Arc-Hole Track-Hole SMDPad-Hole THPad-Hole Via-Hole Fill-Hole Poly-Hole Region-Hole Text-Hole; 0.12: Via-Poly; 0.2: Arc-Fill Arc-Poly Track-Fill Track-Poly SMDPad-SMDPad SMDPad-THPad SMDPad-Fill SMDPad-Poly THPad-THPad THPad-Fill THPad-Poly Via-Via Via-Fill Fill-Fill Fill-Poly Fill-Text Poly-Poly Poly-Region Poly-Text)
Clearance CLEAR_QSPI_BK1 [InNetClass('NET-CLASS_QSPI_BK1')] p12: gap=0.2 ignorepadtopadclearanceinfootprint=FALSE except(0: Arc-Hole Track-Hole SMDPad-Hole THPad-Hole Via-Hole Fill-Hole Poly-Hole Region-Hole Text-Hole; 0.1: Arc-Arc Arc-Track Arc-SMDPad Arc-Via Arc-Region Arc-Text Track-Track Track-SMDPad Track-Via Track-Region Track-Text SMDPad-Via SMDPad-Region SMDPad-Text THPad-Via THPad-Region THPad-Text Via-Region Via-Text Region-Region Region-Text Text-Text; 0.3: Via-Via)
Clearance CLEAR_QSPI_BK2 [InNetClass('NET-CLASS_QSPI_BK2')] p13: gap=0.1 ignorepadtopadclearanceinfootprint=FALSE except(0: Arc-Hole Track-Hole SMDPad-Hole THPad-Hole Via-Hole Fill-Hole Poly-Hole Region-Hole Text-Hole; 0.2: Arc-THPad Arc-Fill Arc-Poly Track-THPad Track-Fill Track-Poly SMDPad-SMDPad SMDPad-THPad SMDPad-Fill SMDPad-Poly THPad-THPad THPad-Fill THPad-Poly Via-Fill Via-Poly Fill-Fill Fill-Poly Poly-Poly Poly-Region Poly-Text; 0.3: Via-Via)
Clearance CLEAR_NAND_X [InNetClass('NET-CLASS_NAND_X')] p14: gap=0.1 ignorepadtopadclearanceinfootprint=FALSE except(0: Arc-Hole Track-Hole SMDPad-Hole THPad-Hole Via-Hole Fill-Hole Poly-Hole Region-Hole Text-Hole; 0.2: Arc-THPad Arc-Fill Arc-Poly Track-THPad Track-Fill Track-Poly SMDPad-SMDPad SMDPad-THPad SMDPad-Fill SMDPad-Poly THPad-THPad THPad-Fill THPad-Poly Via-Fill Via-Poly Fill-Fill Fill-Poly Fill-Region Fill-Text Poly-Poly; 0.3: Via-Via Poly-Region Poly-Text)
Clearance CLEAR_50R_CLK [InNetClass('NET-CLASS_50R_CLK')] p15: gap=0.1 ignorepadtopadclearanceinfootprint=FALSE except(0: Arc-Hole Track-Hole SMDPad-Hole THPad-Hole Via-Hole Fill-Hole Poly-Hole Region-Hole Text-Hole; 0.2: Arc-THPad Track-THPad SMDPad-SMDPad SMDPad-THPad THPad-THPad; 0.3: Track-Track Via-Via; 0.5: Arc-Fill Arc-Poly Track-Fill Track-Poly SMDPad-Fill SMDPad-Poly THPad-Fill THPad-Poly Via-Fill Via-Poly Fill-Fill Fill-Poly Poly-Poly Poly-Region Poly-Text)
Clearance CLEAR_DIFF-100R_DSI_CK [InNetClass('NET-CLASS_DIFF-100R_DSI_CK')] p16: gap=0.1 ignorepadtopadclearanceinfootprint=FALSE except(0: Arc-Hole Track-Hole SMDPad-Hole THPad-Hole Via-Hole Fill-Hole Poly-Hole Region-Hole Text-Hole; 0.13: Track-Track; 0.2: Arc-THPad Track-THPad SMDPad-SMDPad SMDPad-THPad THPad-THPad; 0.3: Via-Via; 0.39: Arc-Fill Arc-Poly Track-Fill Track-Poly SMDPad-Fill SMDPad-Poly THPad-Fill THPad-Poly Via-Fill Via-Poly Fill-Fill Fill-Poly Poly-Poly Poly-Region Poly-Text)
Clearance CLEAR_DIFF-100R_RJ45_D1 [InNetClass('NET-CLASS_DIFF-100R_RJ45_D1')] p17: gap=0.1 ignorepadtopadclearanceinfootprint=FALSE except(0: Arc-Hole Track-Hole SMDPad-Hole THPad-Hole Via-Hole Fill-Hole Poly-Hole Region-Hole Text-Hole; 0.13: Track-Track; 0.2: Arc-THPad Track-THPad SMDPad-SMDPad SMDPad-THPad THPad-THPad; 0.3: Via-Via; 0.39: Arc-Fill Arc-Poly Track-Fill Track-Poly SMDPad-Fill SMDPad-Poly THPad-Fill THPad-Poly Via-Fill Via-Poly Fill-Fill Fill-Poly Poly-Poly Poly-Region Poly-Text)
Clearance CLEAR_DIFF-100R_RJ45_D2 [InNetClass('NET-CLASS_DIFF-100R_RJ45_D2')] p18: gap=0.1 ignorepadtopadclearanceinfootprint=FALSE except(0: Arc-Hole Track-Hole SMDPad-Hole THPad-Hole Via-Hole Fill-Hole Poly-Hole Region-Hole Text-Hole; 0.13: Track-Track; 0.2: Arc-THPad Track-THPad SMDPad-SMDPad SMDPad-THPad THPad-THPad; 0.3: Via-Via; 0.39: Arc-Fill Arc-Poly Track-Fill Track-Poly SMDPad-Fill SMDPad-Poly THPad-Fill THPad-Poly Via-Fill Via-Poly Fill-Fill Fill-Poly Poly-Poly Poly-Region Poly-Text)
Clearance CLEAR_DIFF-100R_RJ45_D3 [InNetClass('NET-CLASS_DIFF-100R_RJ45_D3')] p19: gap=0.1 ignorepadtopadclearanceinfootprint=FALSE except(0: Arc-Hole Track-Hole SMDPad-Hole THPad-Hole Via-Hole Fill-Hole Poly-Hole Region-Hole Text-Hole; 0.13: Track-Track; 0.2: Arc-THPad Track-THPad SMDPad-SMDPad SMDPad-THPad THPad-THPad; 0.3: Via-Via; 0.39: Arc-Fill Arc-Poly Track-Fill Track-Poly SMDPad-Fill SMDPad-Poly THPad-Fill THPad-Poly Via-Fill Via-Poly Fill-Fill Fill-Poly Poly-Poly Poly-Region Poly-Text)
Clearance CLEAR_DIFF-100R_RJ45_D4 [InNetClass('NET-CLASS_DIFF-100R_RJ45_D4')] p20: gap=0.1 ignorepadtopadclearanceinfootprint=FALSE except(0: Arc-Hole Track-Hole SMDPad-Hole THPad-Hole Via-Hole Fill-Hole Poly-Hole Region-Hole Text-Hole; 0.13: Track-Track; 0.2: Arc-THPad Track-THPad SMDPad-SMDPad SMDPad-THPad THPad-THPad; 0.3: Via-Via; 0.39: Arc-Fill Arc-Poly Track-Fill Track-Poly SMDPad-Fill SMDPad-Poly THPad-Fill THPad-Poly Via-Fill Via-Poly Fill-Fill Fill-Poly Poly-Poly Poly-Region Poly-Text)
Clearance CLEAR_DIFF-100R_DSI_D0 [InNetClass('NET-CLASS_DIFF-100R_DSI_D0')] p21: gap=0.1 ignorepadtopadclearanceinfootprint=FALSE except(0: Arc-Hole Track-Hole SMDPad-Hole THPad-Hole Via-Hole Fill-Hole Poly-Hole Region-Hole Text-Hole; 0.13: Track-Track; 0.2: Arc-THPad Track-THPad SMDPad-SMDPad SMDPad-THPad THPad-THPad; 0.3: Via-Via; 0.39: Arc-Fill Arc-Poly Track-Fill Track-Poly SMDPad-Fill SMDPad-Poly THPad-Fill THPad-Poly Via-Fill Via-Poly Fill-Fill Fill-Poly Poly-Poly Poly-Region Poly-Text)
Clearance CLEAR_DIFF-100R_DSI_D1 [InNetClass('NET-CLASS_DIFF-100R_DSI_D1')] p22: gap=0.1 ignorepadtopadclearanceinfootprint=FALSE except(0: Arc-Hole Track-Hole SMDPad-Hole THPad-Hole Via-Hole Fill-Hole Poly-Hole Region-Hole Text-Hole; 0.13: Track-Track; 0.2: Arc-THPad Track-THPad SMDPad-SMDPad SMDPad-THPad THPad-THPad; 0.3: Via-Via; 0.39: Arc-Fill Arc-Poly Track-Fill Track-Poly SMDPad-Fill SMDPad-Poly THPad-Fill THPad-Poly Via-Fill Via-Poly Fill-Fill Fill-Poly Poly-Poly Poly-Region Poly-Text)
Clearance CLEAR_DIFF-90R_USB_DN1 [InNetClass('NET-CLASS_DIFF-90R_USB_DN1')] p23: gap=0.1 ignorepadtopadclearanceinfootprint=FALSE except(0: Arc-Hole Track-Hole SMDPad-Hole THPad-Hole Via-Hole Fill-Hole Poly-Hole Region-Hole Text-Hole; 0.09: Track-Track; 0.2: Arc-THPad Track-THPad SMDPad-SMDPad SMDPad-THPad THPad-THPad; 0.3: Arc-Fill Arc-Poly Track-Fill Track-Poly SMDPad-Fill SMDPad-Poly THPad-Fill THPad-Poly Via-Via Via-Fill Via-Poly Fill-Fill Fill-Poly Poly-Poly Poly-Region Poly-Text)
Clearance CLEAR_DIFF-90R_USB_DN2 [InNetClass('NET-CLASS_DIFF-90R_USB_DN2')] p24: gap=0.1 ignorepadtopadclearanceinfootprint=FALSE except(0: Arc-Hole Track-Hole SMDPad-Hole THPad-Hole Via-Hole Fill-Hole Poly-Hole Region-Hole Text-Hole; 0.09: Track-Track; 0.2: Arc-THPad Track-THPad SMDPad-SMDPad SMDPad-THPad THPad-THPad; 0.3: Arc-Fill Arc-Poly Track-Fill Track-Poly SMDPad-Fill SMDPad-Poly THPad-Fill THPad-Poly Via-Via Via-Fill Via-Poly Fill-Fill Fill-Poly Poly-Poly Poly-Region Poly-Text)
Clearance CLEAR_DIFF-90R_USB_DN3 [InNetClass('NET-CLASS_DIFF-90R_USB_DN3')] p25: gap=0.1 ignorepadtopadclearanceinfootprint=FALSE except(0: Arc-Hole Track-Hole SMDPad-Hole THPad-Hole Via-Hole Fill-Hole Poly-Hole Region-Hole Text-Hole; 0.09: Track-Track; 0.2: Arc-THPad Track-THPad SMDPad-SMDPad SMDPad-THPad THPad-THPad; 0.3: Arc-Fill Arc-Poly Track-Fill Track-Poly SMDPad-Fill SMDPad-Poly THPad-Fill THPad-Poly Via-Via Via-Fill Via-Poly Fill-Fill Fill-Poly Poly-Poly Poly-Region Poly-Text)
Clearance CLEAR_DIFF-90R_USB_DN4 [InNetClass('NET-CLASS_DIFF-90R_USB_DN4')] p26: gap=0.1 ignorepadtopadclearanceinfootprint=FALSE except(0: Arc-Hole Track-Hole SMDPad-Hole THPad-Hole Via-Hole Fill-Hole Poly-Hole Region-Hole Text-Hole; 0.09: Track-Track; 0.2: Arc-THPad Track-THPad SMDPad-SMDPad SMDPad-THPad THPad-THPad; 0.3: Arc-Fill Arc-Poly Track-Fill Track-Poly SMDPad-Fill SMDPad-Poly THPad-Fill THPad-Poly Via-Via Via-Fill Via-Poly Fill-Fill Fill-Poly Poly-Poly Poly-Region Poly-Text)
Clearance CLEAR_DIFF-90R_USB_AB [InNetClass('NET-CLASS_DIFF-90R_USB_AB')] p27: gap=0.1 ignorepadtopadclearanceinfootprint=FALSE except(0: Arc-Hole Track-Hole SMDPad-Hole THPad-Hole Via-Hole Fill-Hole Poly-Hole Region-Hole Text-Hole; 0.09: Track-Track; 0.2: Arc-THPad Track-THPad SMDPad-SMDPad SMDPad-THPad THPad-THPad; 0.3: Arc-Fill Arc-Poly Track-Fill Track-Poly SMDPad-Fill SMDPad-Poly THPad-Fill THPad-Poly Via-Via Via-Fill Via-Poly Fill-Fill Fill-Poly Poly-Poly Poly-Region Poly-Text)
Clearance CLEAR_DIFF-90R_USB_CON [InNetClass('NET-CLASS_DIFF-90R_USB_CON')] p28: gap=0.1 ignorepadtopadclearanceinfootprint=FALSE except(0: Arc-Hole Track-Hole SMDPad-Hole THPad-Hole Via-Hole Fill-Hole Poly-Hole Region-Hole Text-Hole; 0.09: Track-Track; 0.2: Arc-THPad Track-THPad SMDPad-SMDPad SMDPad-THPad THPad-THPad; 0.3: Arc-Fill Arc-Poly Track-Fill Track-Poly SMDPad-Fill SMDPad-Poly THPad-Fill THPad-Poly Via-Via Via-Fill Via-Poly Fill-Fill Fill-Poly Poly-Poly Poly-Region Poly-Text)
Clearance CLEAR_DIFF-90R_USB_HUB [InNetClass('NET-CLASS_DIFF-90R_USB_HUB')] p29: gap=0.1 ignorepadtopadclearanceinfootprint=FALSE except(0: Arc-Hole Track-Hole SMDPad-Hole THPad-Hole Via-Hole Fill-Hole Poly-Hole Region-Hole Text-Hole; 0.09: Track-Track; 0.2: Arc-THPad Track-THPad SMDPad-SMDPad SMDPad-THPad THPad-THPad; 0.3: Arc-Fill Arc-Poly Track-Fill Track-Poly SMDPad-Fill SMDPad-Poly THPad-Fill THPad-Poly Via-Via Via-Fill Via-Poly Fill-Fill Fill-Poly Poly-Poly Poly-Region Poly-Text)
Clearance CLEAR_DIFF-90R_USB1_CN25 [InNetClass('NET-CLASS_DIFF-90R_USB1_CN25')] p30: gap=0.1 ignorepadtopadclearanceinfootprint=FALSE except(0: Arc-Hole Track-Hole SMDPad-Hole THPad-Hole Via-Hole Fill-Hole Poly-Hole Region-Hole Text-Hole; 0.09: Track-Track; 0.2: Arc-THPad Track-THPad SMDPad-SMDPad SMDPad-THPad THPad-THPad; 0.3: Arc-Fill Arc-Poly Track-Fill Track-Poly SMDPad-Fill SMDPad-Poly THPad-Fill THPad-Poly Via-Via Via-Fill Via-Poly Fill-Fill Fill-Poly Poly-Poly Poly-Region Poly-Text)
Clearance CLEAR_DIFF-90R_USB2_CN25 [InNetClass('NET-CLASS_DIFF-90R_USB2_CN25')] p31: gap=0.1 ignorepadtopadclearanceinfootprint=FALSE except(0: Arc-Hole Track-Hole SMDPad-Hole THPad-Hole Via-Hole Fill-Hole Poly-Hole Region-Hole Text-Hole; 0.09: Track-Track; 0.2: Arc-THPad Track-THPad SMDPad-SMDPad SMDPad-THPad THPad-THPad; 0.3: Arc-Fill Arc-Poly Track-Fill Track-Poly SMDPad-Fill SMDPad-Poly THPad-Fill THPad-Poly Via-Via Via-Fill Via-Poly Fill-Fill Fill-Poly Poly-Poly Poly-Region Poly-Text)
Clearance CLEAR_DIFF-90R_USB3_CN26 [InNetClass('NET-CLASS_DIFF-90R_USB3_CN26')] p32: gap=0.1 ignorepadtopadclearanceinfootprint=FALSE except(0: Arc-Hole Track-Hole SMDPad-Hole THPad-Hole Via-Hole Fill-Hole Poly-Hole Region-Hole Text-Hole; 0.09: Track-Track; 0.2: Arc-THPad Track-THPad SMDPad-SMDPad SMDPad-THPad THPad-THPad; 0.3: Arc-Fill Arc-Poly Track-Fill Track-Poly SMDPad-Fill SMDPad-Poly THPad-Fill THPad-Poly Via-Via Via-Fill Via-Poly Fill-Fill Fill-Poly Poly-Poly Poly-Region Poly-Text)
Clearance CLEAR_DIFF-90R_USB4_CN26 [InNetClass('NET-CLASS_DIFF-90R_USB4_CN26')] p33: gap=0.1 ignorepadtopadclearanceinfootprint=FALSE except(0: Arc-Hole Track-Hole SMDPad-Hole THPad-Hole Via-Hole Fill-Hole Poly-Hole Region-Hole Text-Hole; 0.09: Track-Track; 0.2: Arc-THPad Track-THPad SMDPad-SMDPad SMDPad-THPad THPad-THPad; 0.3: Arc-Fill Arc-Poly Track-Fill Track-Poly SMDPad-Fill SMDPad-Poly THPad-Fill THPad-Poly Via-Via Via-Fill Via-Poly Fill-Fill Fill-Poly Poly-Poly Poly-Region Poly-Text)
Clearance CLEAR_GND [InNetClass('NET-CLASS_GND')] p34: gap=0.1 ignorepadtopadclearanceinfootprint=FALSE except(0: Arc-Hole Track-Hole SMDPad-Hole THPad-Hole Via-Hole Fill-Hole Poly-Hole Region-Hole Text-Hole; 0.2: Arc-Fill Arc-Poly Track-Fill Track-Poly SMDPad-Fill SMDPad-Poly THPad-Fill THPad-Poly Via-Fill Via-Poly Fill-Fill Fill-Poly Fill-Region Fill-Text Poly-Poly Poly-Region Poly-Text)
Clearance CLEAR_ALIMS [InNetClass('NET-CLASS_ALIMS')] p35: gap=0.1 ignorepadtopadclearanceinfootprint=FALSE except(0: Arc-Hole Track-Hole SMDPad-Hole THPad-Hole Via-Hole Fill-Hole Poly-Hole Region-Hole Text-Hole; 0.2: Arc-THPad Arc-Fill Arc-Poly Track-THPad Track-Fill Track-Poly SMDPad-SMDPad SMDPad-THPad SMDPad-Fill SMDPad-Poly THPad-THPad THPad-Fill THPad-Poly Via-Via Via-Fill Via-Poly Fill-Fill Fill-Poly Poly-Poly Poly-Region Poly-Text)
Clearance [All] p36: gap=0.1 ignorepadtopadclearanceinfootprint=FALSE except(0: Arc-Hole Track-Hole SMDPad-Hole THPad-Hole Via-Hole Fill-Hole Poly-Hole Region-Hole Text-Hole; 0.2: Arc-THPad Arc-Fill Arc-Poly Track-THPad Track-Fill Track-Poly SMDPad-SMDPad SMDPad-THPad SMDPad-Fill SMDPad-Poly THPad-THPad THPad-Fill THPad-Poly Via-Fill Via-Poly Fill-Fill Fill-Poly Poly-Poly Poly-Region Poly-Text; 0.3: Via-Via)
ComponentClearance [All] p1 off: gap=0.025 collisioncheckmode=3 verticalgap=2540 showdistances=TRUE
DiffPairsRouting DIFF-100R_RJ45_D1 [InDifferentialPairClass('DIFF-CLASS_DIFF-100R_RJ45_D1')] p1: maxlimit=0.13 minlimit=0.13 mostfreqgap=0.13 toplayer_minwidth=0.1 toplayer_maxwidth=0.1 toplayer_prefwidth=0.1 midlayer1_minwidth=0.1 midlayer1_maxwidth=0.1 midlayer1_prefwidth=0.1 midlayer2_minwidth=0.1 midlayer2_maxwidth=0.1 midlayer2_prefwidth=0.1 midlayer3_minwidth=0.1 midlayer3_maxwidth=0.1 midlayer3_prefwidth=0.1 midlayer4_minwidth=0.1 midlayer4_maxwidth=0.1 midlayer4_prefwidth=0.1 bottomlayer_minwidth=0.1 bottomlayer_maxwidth=0.1 bottomlayer_prefwidth=0.1 maxuncoupledlength=12.7
DiffPairsRouting DIFF-100R_RJ45_D2 [InDifferentialPairClass('DIFF-CLASS_DIFF-100R_RJ45_D2')] p2: maxlimit=0.13 minlimit=0.13 mostfreqgap=0.13 toplayer_minwidth=0.1 toplayer_maxwidth=0.1 toplayer_prefwidth=0.1 midlayer1_minwidth=0.1 midlayer1_maxwidth=0.1 midlayer1_prefwidth=0.1 midlayer2_minwidth=0.1 midlayer2_maxwidth=0.1 midlayer2_prefwidth=0.1 midlayer3_minwidth=0.1 midlayer3_maxwidth=0.1 midlayer3_prefwidth=0.1 midlayer4_minwidth=0.1 midlayer4_maxwidth=0.1 midlayer4_prefwidth=0.1 bottomlayer_minwidth=0.1 bottomlayer_maxwidth=0.1 bottomlayer_prefwidth=0.1 maxuncoupledlength=12.7
DiffPairsRouting DIFF-100R_RJ45_D3 [InDifferentialPairClass('DIFF-CLASS_DIFF-100R_RJ45_D3')] p3: maxlimit=0.13 minlimit=0.13 mostfreqgap=0.13 toplayer_minwidth=0.1 toplayer_maxwidth=0.1 toplayer_prefwidth=0.1 midlayer1_minwidth=0.1 midlayer1_maxwidth=0.1 midlayer1_prefwidth=0.1 midlayer2_minwidth=0.1 midlayer2_maxwidth=0.1 midlayer2_prefwidth=0.1 midlayer3_minwidth=0.1 midlayer3_maxwidth=0.1 midlayer3_prefwidth=0.1 midlayer4_minwidth=0.1 midlayer4_maxwidth=0.1 midlayer4_prefwidth=0.1 bottomlayer_minwidth=0.1 bottomlayer_maxwidth=0.1 bottomlayer_prefwidth=0.1 maxuncoupledlength=12.7
DiffPairsRouting DIFF-100R_RJ45_D4 [InDifferentialPairClass('DIFF-CLASS_DIFF-100R_RJ45_D4')] p4: maxlimit=0.13 minlimit=0.13 mostfreqgap=0.13 toplayer_minwidth=0.1 toplayer_maxwidth=0.1 toplayer_prefwidth=0.1 midlayer1_minwidth=0.1 midlayer1_maxwidth=0.1 midlayer1_prefwidth=0.1 midlayer2_minwidth=0.1 midlayer2_maxwidth=0.1 midlayer2_prefwidth=0.1 midlayer3_minwidth=0.1 midlayer3_maxwidth=0.1 midlayer3_prefwidth=0.1 midlayer4_minwidth=0.1 midlayer4_maxwidth=0.1 midlayer4_prefwidth=0.1 bottomlayer_minwidth=0.1 bottomlayer_maxwidth=0.1 bottomlayer_prefwidth=0.1 maxuncoupledlength=12.7
DiffPairsRouting DIFF-90R_USB_DN1 [InDifferentialPairClass('DIFF-CLASS_DIFF-90R_USB_DN1')] p5: maxlimit=0.09 minlimit=0.09 mostfreqgap=0.09 toplayer_minwidth=0.1 toplayer_maxwidth=0.1 toplayer_prefwidth=0.1 midlayer1_minwidth=0.1 midlayer1_maxwidth=0.1 midlayer1_prefwidth=0.1 midlayer2_minwidth=0.1 midlayer2_maxwidth=0.1 midlayer2_prefwidth=0.1 midlayer3_minwidth=0.1 midlayer3_maxwidth=0.1 midlayer3_prefwidth=0.1 midlayer4_minwidth=0.1 midlayer4_maxwidth=0.1 midlayer4_prefwidth=0.1 bottomlayer_minwidth=0.1 bottomlayer_maxwidth=0.1 bottomlayer_prefwidth=0.1 maxuncoupledlength=12.7
DiffPairsRouting DIFF-90R_USB_DN2 [InDifferentialPairClass('DIFF-CLASS_DIFF-90R_USB_DN2')] p6: maxlimit=0.09 minlimit=0.09 mostfreqgap=0.09 toplayer_minwidth=0.1 toplayer_maxwidth=0.1 toplayer_prefwidth=0.1 midlayer1_minwidth=0.1 midlayer1_maxwidth=0.1 midlayer1_prefwidth=0.1 midlayer2_minwidth=0.1 midlayer2_maxwidth=0.1 midlayer2_prefwidth=0.1 midlayer3_minwidth=0.1 midlayer3_maxwidth=0.1 midlayer3_prefwidth=0.1 midlayer4_minwidth=0.1 midlayer4_maxwidth=0.1 midlayer4_prefwidth=0.1 bottomlayer_minwidth=0.1 bottomlayer_maxwidth=0.1 bottomlayer_prefwidth=0.1 maxuncoupledlength=12.7
DiffPairsRouting DIFF-90R_USB_DN3 [InDifferentialPairClass('DIFF-CLASS_DIFF-90R_USB_DN3')] p7: maxlimit=0.09 minlimit=0.09 mostfreqgap=0.09 toplayer_minwidth=0.1 toplayer_maxwidth=0.1 toplayer_prefwidth=0.1 midlayer1_minwidth=0.1 midlayer1_maxwidth=0.1 midlayer1_prefwidth=0.1 midlayer2_minwidth=0.1 midlayer2_maxwidth=0.1 midlayer2_prefwidth=0.1 midlayer3_minwidth=0.1 midlayer3_maxwidth=0.1 midlayer3_prefwidth=0.1 midlayer4_minwidth=0.1 midlayer4_maxwidth=0.1 midlayer4_prefwidth=0.1 bottomlayer_minwidth=0.1 bottomlayer_maxwidth=0.1 bottomlayer_prefwidth=0.1 maxuncoupledlength=12.7
DiffPairsRouting DIFF-90R_USB_DN4 [InDifferentialPairClass('DIFF-CLASS_DIFF-90R_USB_DN4')] p8: maxlimit=0.09 minlimit=0.09 mostfreqgap=0.09 toplayer_minwidth=0.1 toplayer_maxwidth=0.1 toplayer_prefwidth=0.1 midlayer1_minwidth=0.1 midlayer1_maxwidth=0.1 midlayer1_prefwidth=0.1 midlayer2_minwidth=0.1 midlayer2_maxwidth=0.1 midlayer2_prefwidth=0.1 midlayer3_minwidth=0.1 midlayer3_maxwidth=0.1 midlayer3_prefwidth=0.1 midlayer4_minwidth=0.1 midlayer4_maxwidth=0.1 midlayer4_prefwidth=0.1 bottomlayer_minwidth=0.1 bottomlayer_maxwidth=0.1 bottomlayer_prefwidth=0.1 maxuncoupledlength=12.7
DiffPairsRouting DIFF-90R_USB1_CN25 [InDifferentialPairClass('DIFF-CLASS_DIFF-90R_USB1_CN25')] p9: maxlimit=0.09 minlimit=0.09 mostfreqgap=0.09 toplayer_minwidth=0.1 toplayer_maxwidth=0.1 toplayer_prefwidth=0.1 midlayer1_minwidth=0.1 midlayer1_maxwidth=0.1 midlayer1_prefwidth=0.1 midlayer2_minwidth=0.1 midlayer2_maxwidth=0.1 midlayer2_prefwidth=0.1 midlayer3_minwidth=0.1 midlayer3_maxwidth=0.1 midlayer3_prefwidth=0.1 midlayer4_minwidth=0.1 midlayer4_maxwidth=0.1 midlayer4_prefwidth=0.1 bottomlayer_minwidth=0.1 bottomlayer_maxwidth=0.1 bottomlayer_prefwidth=0.1 maxuncoupledlength=12.7
DiffPairsRouting DIFF-90R_USB2_CN25 [InDifferentialPairClass('DIFF-CLASS_DIFF-90R_USB2_CN25')] p10: maxlimit=0.09 minlimit=0.09 mostfreqgap=0.09 toplayer_minwidth=0.1 toplayer_maxwidth=0.1 toplayer_prefwidth=0.1 midlayer1_minwidth=0.1 midlayer1_maxwidth=0.1 midlayer1_prefwidth=0.1 midlayer2_minwidth=0.1 midlayer2_maxwidth=0.1 midlayer2_prefwidth=0.1 midlayer3_minwidth=0.1 midlayer3_maxwidth=0.1 midlayer3_prefwidth=0.1 midlayer4_minwidth=0.1 midlayer4_maxwidth=0.1 midlayer4_prefwidth=0.1 bottomlayer_minwidth=0.1 bottomlayer_maxwidth=0.1 bottomlayer_prefwidth=0.1 maxuncoupledlength=12.7
DiffPairsRouting DIFF-90R_USB3_CN26 [InDifferentialPairClass('DIFF-CLASS_DIFF-90R_USB3_CN26')] p11: maxlimit=0.09 minlimit=0.09 mostfreqgap=0.09 toplayer_minwidth=0.1 toplayer_maxwidth=0.1 toplayer_prefwidth=0.1 midlayer1_minwidth=0.1 midlayer1_maxwidth=0.1 midlayer1_prefwidth=0.1 midlayer2_minwidth=0.1 midlayer2_maxwidth=0.1 midlayer2_prefwidth=0.1 midlayer3_minwidth=0.1 midlayer3_maxwidth=0.1 midlayer3_prefwidth=0.1 midlayer4_minwidth=0.1 midlayer4_maxwidth=0.1 midlayer4_prefwidth=0.1 bottomlayer_minwidth=0.1 bottomlayer_maxwidth=0.1 bottomlayer_prefwidth=0.1 maxuncoupledlength=12.7
DiffPairsRouting DIFF-90R_USB4_CN26 [InDifferentialPairClass('DIFF-CLASS_DIFF-90R_USB4_CN26')] p12: maxlimit=0.09 minlimit=0.09 mostfreqgap=0.09 toplayer_minwidth=0.1 toplayer_maxwidth=0.1 toplayer_prefwidth=0.1 midlayer1_minwidth=0.1 midlayer1_maxwidth=0.1 midlayer1_prefwidth=0.1 midlayer2_minwidth=0.1 midlayer2_maxwidth=0.1 midlayer2_prefwidth=0.1 midlayer3_minwidth=0.1 midlayer3_maxwidth=0.1 midlayer3_prefwidth=0.1 midlayer4_minwidth=0.1 midlayer4_maxwidth=0.1 midlayer4_prefwidth=0.1 bottomlayer_minwidth=0.1 bottomlayer_maxwidth=0.1 bottomlayer_prefwidth=0.1 maxuncoupledlength=12.7
DiffPairsRouting DIFF-90R_USB_AB [InDifferentialPairClass('DIFF-CLASS_DIFF-90R_USB_AB')] p13: maxlimit=0.09 minlimit=0.09 mostfreqgap=0.09 toplayer_minwidth=0.1 toplayer_maxwidth=0.1 toplayer_prefwidth=0.1 midlayer1_minwidth=0.1 midlayer1_maxwidth=0.1 midlayer1_prefwidth=0.1 midlayer2_minwidth=0.1 midlayer2_maxwidth=0.1 midlayer2_prefwidth=0.1 midlayer3_minwidth=0.1 midlayer3_maxwidth=0.1 midlayer3_prefwidth=0.1 midlayer4_minwidth=0.1 midlayer4_maxwidth=0.1 midlayer4_prefwidth=0.1 bottomlayer_minwidth=0.1 bottomlayer_maxwidth=0.1 bottomlayer_prefwidth=0.1 maxuncoupledlength=12.7
DiffPairsRouting DIFF-90R_USB_CON [InDifferentialPairClass('DIFF-CLASS_DIFF-90R_USB_CON')] p14: maxlimit=0.09 minlimit=0.09 mostfreqgap=0.09 toplayer_minwidth=0.1 toplayer_maxwidth=0.1 toplayer_prefwidth=0.1 midlayer1_minwidth=0.1 midlayer1_maxwidth=0.1 midlayer1_prefwidth=0.1 midlayer2_minwidth=0.1 midlayer2_maxwidth=0.1 midlayer2_prefwidth=0.1 midlayer3_minwidth=0.1 midlayer3_maxwidth=0.1 midlayer3_prefwidth=0.1 midlayer4_minwidth=0.1 midlayer4_maxwidth=0.1 midlayer4_prefwidth=0.1 bottomlayer_minwidth=0.1 bottomlayer_maxwidth=0.1 bottomlayer_prefwidth=0.1 maxuncoupledlength=12.7
DiffPairsRouting DIFF-90R_USB_HUB [InDifferentialPairClass('DIFF-CLASS_DIFF-90R_USB_HUB')] p15: maxlimit=0.09 minlimit=0.09 mostfreqgap=0.09 toplayer_minwidth=0.1 toplayer_maxwidth=0.1 toplayer_prefwidth=0.1 midlayer1_minwidth=0.1 midlayer1_maxwidth=0.1 midlayer1_prefwidth=0.1 midlayer2_minwidth=0.1 midlayer2_maxwidth=0.1 midlayer2_prefwidth=0.1 midlayer3_minwidth=0.1 midlayer3_maxwidth=0.1 midlayer3_prefwidth=0.1 midlayer4_minwidth=0.1 midlayer4_maxwidth=0.1 midlayer4_prefwidth=0.1 bottomlayer_minwidth=0.1 bottomlayer_maxwidth=0.1 bottomlayer_prefwidth=0.1 maxuncoupledlength=12.7
DiffPairsRouting DIFF-100R_DSI_CK [InDifferentialPairClass('DIFF-CLASS_DIFF-100R_DSI_CK')] p16: maxlimit=0.13 minlimit=0.13 mostfreqgap=0.13 toplayer_minwidth=0.1 toplayer_maxwidth=0.1 toplayer_prefwidth=0.1 midlayer1_minwidth=0.1 midlayer1_maxwidth=0.1 midlayer1_prefwidth=0.1 midlayer2_minwidth=0.1 midlayer2_maxwidth=0.1 midlayer2_prefwidth=0.1 midlayer3_minwidth=0.1 midlayer3_maxwidth=0.1 midlayer3_prefwidth=0.1 midlayer4_minwidth=0.1 midlayer4_maxwidth=0.1 midlayer4_prefwidth=0.1 bottomlayer_minwidth=0.1 bottomlayer_maxwidth=0.1 bottomlayer_prefwidth=0.1 maxuncoupledlength=12.7
DiffPairsRouting DIFF-100R_DSI_D0 [InDifferentialPairClass('DIFF-CLASS_DIFF-100R_DSI_D0')] p17: maxlimit=0.13 minlimit=0.13 mostfreqgap=0.13 toplayer_minwidth=0.1 toplayer_maxwidth=0.1 toplayer_prefwidth=0.1 midlayer1_minwidth=0.1 midlayer1_maxwidth=0.1 midlayer1_prefwidth=0.1 midlayer2_minwidth=0.1 midlayer2_maxwidth=0.1 midlayer2_prefwidth=0.1 midlayer3_minwidth=0.1 midlayer3_maxwidth=0.1 midlayer3_prefwidth=0.1 midlayer4_minwidth=0.1 midlayer4_maxwidth=0.1 midlayer4_prefwidth=0.1 bottomlayer_minwidth=0.1 bottomlayer_maxwidth=0.1 bottomlayer_prefwidth=0.1 maxuncoupledlength=12.7
DiffPairsRouting DIFF-100R_DSI_D1 [InDifferentialPairClass('DIFF-CLASS_DIFF-100R_DSI_D1')] p18: maxlimit=0.13 minlimit=0.13 mostfreqgap=0.13 toplayer_minwidth=0.1 toplayer_maxwidth=0.1 toplayer_prefwidth=0.1 midlayer1_minwidth=0.1 midlayer1_maxwidth=0.1 midlayer1_prefwidth=0.1 midlayer2_minwidth=0.1 midlayer2_maxwidth=0.1 midlayer2_prefwidth=0.1 midlayer3_minwidth=0.1 midlayer3_maxwidth=0.1 midlayer3_prefwidth=0.1 midlayer4_minwidth=0.1 midlayer4_maxwidth=0.1 midlayer4_prefwidth=0.1 bottomlayer_minwidth=0.1 bottomlayer_maxwidth=0.1 bottomlayer_prefwidth=0.1 maxuncoupledlength=12.7
DiffPairsRouting [All] p19: maxlimit=0.254 minlimit=0.254 mostfreqgap=0.254 toplayer_minwidth=0.381 toplayer_maxwidth=0.381 toplayer_prefwidth=0.381 midlayer1_minwidth=0.381 midlayer1_maxwidth=0.381 midlayer1_prefwidth=0.381 midlayer2_minwidth=0.381 midlayer2_maxwidth=0.381 midlayer2_prefwidth=0.381 midlayer3_minwidth=0.381 midlayer3_maxwidth=0.381 midlayer3_prefwidth=0.381 midlayer4_minwidth=0.381 midlayer4_maxwidth=0.381 midlayer4_prefwidth=0.381 bottomlayer_minwidth=0.381 bottomlayer_maxwidth=0.381 bottomlayer_prefwidth=0.381 maxuncoupledlength=12.7
FanoutControl Fanout_BGA [IsBGA] p1: bgadir=Out bgaviamode=Closest fanoutstyle=Auto fanoutdirection=Alternating viagrid=0.025 // Fanout_BGA (Default Rule)
FanoutControl Fanout_LCC [IsLCC] p2: bgadir=Out bgaviamode=Closest fanoutstyle=Auto fanoutdirection=Alternating viagrid=0.025 // Fanout_LCC (Default Rule)
FanoutControl Fanout_SOIC [IsSOIC] p3: bgadir=Out bgaviamode=Closest fanoutstyle=Auto fanoutdirection=Alternating viagrid=0.025 // Fanout_SOIC (Default Rule)
FanoutControl Fanout_Small [(CompPinCount < 5)] p4: bgadir=Out bgaviamode=Closest fanoutstyle=Auto fanoutdirection=OutThenIn viagrid=0.025 // Fanout_Small (Default Rule)
FanoutControl Fanout_Default [All] p5: bgadir=Out bgaviamode=Closest fanoutstyle=Auto fanoutdirection=Alternating viagrid=0.025 // Fanout_Default (Default Rule)
Height [All] p1 off: minheight=0 maxheight=100 prefheight=0.5
HoleSize [All] p1: absolutevalues=TRUE maxlimit=10 minlimit=0.15 maxpercent=80.000 minpercent=20.000
HoleToHoleClearance [All] p1: gap=0.35 allowstackedmicrovias=TRUE
MatchedLengths LENGTH_50R_RGMII_ETH-RX [InNetClass('NET-CLASS_50R_RGMII_ETH-RX')] p1: tolerance=10.16 checknetsindiffpair=FALSE checkdiffpairvsdiffpair=TRUE checkxsignals=TRUE checkothers=TRUE
MatchedLengths LENGTH_50R_RGMII_ETH-TX [InNetClass('NET-CLASS_50R_RGMII_ETH-TX')] p2: tolerance=10.16 checknetsindiffpair=FALSE checkdiffpairvsdiffpair=TRUE checkxsignals=TRUE checkothers=TRUE
MatchedLengths LENGTH_DSI [Not All] p3: tolerance=5 checknetsindiffpair=FALSE checkdiffpairvsdiffpair=TRUE checkxsignals=TRUE checkothers=TRUE
MinimumSolderMaskSliver [All] p1: minsoldermaskwidth=0
PlaneClearance [All] p1: clearance=0.6
PlaneConnect [All] p1: planeconnectstyle=Relief reliefexpansion=0.5 reliefentries=4 reliefconductorwidth=0.3 reliefairgap=0.2
PolygonConnect plans_alim_interne_1 [All vs IsPad] p1: connectstyle=Relief reliefconductorwidth=0.15 reliefentries=4 polygonreliefangle="90 Angle" airgapwidth=0.15
PolygonConnect PolygonConnect_1 [IsVia vs IsNamedPolygon('VDD_L04_P010')] p2: connectstyle=Direct reliefconductorwidth=0.254 reliefentries=4 polygonreliefangle="90 Angle" airgapwidth=0.254
PolygonConnect [All] p3: connectstyle=Direct reliefconductorwidth=0.3 reliefentries=4 polygonreliefangle="90 Angle" airgapwidth=0.3
RoutingVias VIA_BGA050-AUDIO [InNetClass('NET-CLASS_BGA050-AUDIO_VIA')] p1: holewidth=0.15 width=0.3 viastyle="Through Hole" minholewidth=0.15 minwidth=0.3 maxholewidth=0.15 maxwidth=0.3
RoutingVias VIA_DIFF-90R [InNetClass('NET-CLASS_DIFF-90R_VIA')] p2: holewidth=0.2 width=0.4 viastyle="Through Hole" minholewidth=0.2 minwidth=0.4 maxholewidth=0.2 maxwidth=0.4
RoutingVias VIA_BGA080 [InNetClass('NET-CLASS_BGA080_VIA')] p3: holewidth=0.2 width=0.6 viastyle="Through Hole" minholewidth=0.2 minwidth=0.4 maxholewidth=0.2 maxwidth=0.4
RoutingVias VIA_BGA100 [InNetClass('NET-CLASS_BGA100_VIA')] p4: holewidth=0.2 width=0.4 viastyle="Through Hole" minholewidth=0.2 minwidth=0.4 maxholewidth=0.2 maxwidth=0.4
RoutingVias VIA_ALIMS [InNetClass('NET-CLASS_ALIMS')] p5: holewidth=0.2 width=0.4 viastyle="Through Hole" minholewidth=0.15 minwidth=0.3 maxholewidth=0.3 maxwidth=0.6
RoutingVias VIA_GND [InNetClass('NET-CLASS_GND')] p6: holewidth=0.3 width=0.6 viastyle="Through Hole" minholewidth=0.15 minwidth=0.3 maxholewidth=0.3 maxwidth=0.6
RoutingVias [All] p7: holewidth=0.3 width=0.6 viastyle="Through Hole" minholewidth=0.3 minwidth=0.6 maxholewidth=0.3 maxwidth=0.6
SilkToSilkClearance [All] p1: silktosilkclearance=0
SilkToSolderMaskClearance [IsPad] p1: minsilkscreentomaskgap=0 clearancetoexposedcopper=TRUE
SolderMaskExpansion [All] p1: expansion=0.05
Width WIDTH_50R_RGMII_ETH-TX [InNetClass('NET-CLASS_50R_RGMII_ETH-TX')] p1: maxlimit=0.25 minlimit=0.13 preferedwidth=0.25 toplayer_maxwidth=0.13 toplayer_prefwidth=0.13 midlayer1_maxwidth=0.13 midlayer1_prefwidth=0.13 midlayer2_maxwidth=0.13 midlayer2_prefwidth=0.13 midlayer3_maxwidth=0.13 midlayer3_prefwidth=0.13 midlayer4_minwidth=0.25 bottomlayer_maxwidth=0.13 bottomlayer_prefwidth=0.13 minimp=50.000000 maximp=50.000000 favimp=50.000000
Width WIDTH_50R_JTAG_JT [InNetClass('NET-CLASS_50R_RGMII_ETH-TX')] p2: maxlimit=0.13 minlimit=0.13 preferedwidth=0.13
Width WIDTH_50R_DCMI [InNetClass('NET-CLASS_50R_DCMI')] p3: maxlimit=0.13 minlimit=0.13 preferedwidth=0.13
Width WIDTH_NAND_D [InNetClass('NET-CLASS_NAND_D')] p4: maxlimit=0.1 minlimit=0.1 preferedwidth=0.1
Width WIDTH_ALIMS [InNetClass('NET-CLASS_ALIMS')] p5: maxlimit=1 minlimit=0.2 preferedwidth=0.3
Width WIDTH_GND [InNetClass('NET-CLASS_GND')] p6: maxlimit=1 minlimit=0.2 preferedwidth=0.3
Width WIDTH_QSPI_BK1 [InNetClass('NET-CLASS_QSPI_BK1')] p7: maxlimit=0.1 minlimit=0.1 preferedwidth=0.1
Width WIDTH_QSPI_BK2 [InNetClass('NET-CLASS_QSPI_BK2')] p8: maxlimit=0.1 minlimit=0.1 preferedwidth=0.1
Width WIDTH_NAND_X [InNetClass('NET-CLASS_NAND_X')] p9: maxlimit=0.1 minlimit=0.1 preferedwidth=0.1
Width WIDTH_50R_TRACE-RGB_TRACED-LTDC [InNetClass('NET-CLASS_50R_TRACE-RGB_TRACED-LTDC')] p10: maxlimit=0.13 minlimit=0.13 preferedwidth=0.13
Width WIDTH_50R_CLK [InNetClass('NET-CLASS_50R_CLK')] p11: maxlimit=0.13 minlimit=0.13 preferedwidth=0.13
Width WIDTH_50R_RGMII_ETH-RX [InNetClass('NET-CLASS_50R_RGMII_ETH-RX')] p12: maxlimit=0.25 minlimit=0.13 preferedwidth=0.25 toplayer_maxwidth=0.13 toplayer_prefwidth=0.13 midlayer1_maxwidth=0.13 midlayer1_prefwidth=0.13 midlayer2_maxwidth=0.13 midlayer2_prefwidth=0.13 midlayer3_maxwidth=0.13 midlayer3_prefwidth=0.13 midlayer4_minwidth=0.25 bottomlayer_maxwidth=0.13 bottomlayer_prefwidth=0.13 minimp=50.000000 maximp=50.000000 favimp=50.000000
Width [All] p13: maxlimit=10 minlimit=0.1 preferedwidth=0.1
15 further rules are at their usual default settings.

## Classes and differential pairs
polygon class PolygonClass_1: NONET_L01_P008
polygon class plans_alim_interne: NONET_L04_P010
net class NET-CLASS_BGA050-AUDIO_VIA: NetC19_1 NetC21_1 NetC22_1 NetC22_2 NetC23_2 NetC24_2 NetC26_1 NetC31_2 NetC36_2 NetC38_2 NetC39_1 NetC39_2 NetC44_2 NetC45_2 NetC46_2 NetJP3_3 NetJP6_1 NetR40_2 NetR43_1 NetR49_1 NetR50_1 NetR54_2 NetSB4_1 NetSB7_2 NetSB9_2 NetSB10_2 NetTP10_1 NetTP11_1 NetU8_G3
net class NET-CLASS_BGA100_VIA: NetR88_2 NetR124_2 NRST QSPI_BK1_IO0 QSPI_BK1_IO1 QSPI_BK1_IO2 QSPI_BK1_IO3 QSPI_BK2_IO0 QSPI_BK2_IO1 QSPI_BK2_IO2 QSPI_BK2_IO3 QSPI_CLK
net class NET-CLASS_BGA080_VIA: NAND_ALE NAND_CLE NAND_D0 NAND_D1 NAND_D2 NAND_D3 NAND_D4 NAND_D5 NAND_D6 NAND_D7 NAND_NCE NAND_NOE NAND_NWAIT NAND_NWE NetJP5_2
net class NET-CLASS_DIFF-90R_VIA: USB1CN25_N USB1CN25_P USB2CN25_N USB2CN25_P USB3CN26_N USB3CN26_P USB4CN26_N USB4CN26_P USB_AB_N USB_AB_P USB_CON_N USB_CON_P USB_HUB_N USB_HUB_P USBDN1_N USBDN1_P USBDN2_N USBDN2_P USBDN3_N USBDN3_P USBDN4_N USBDN4_P
net class NET-CLASS_GND: GND
net class NET-CLASS_ALIMS: 1V05_AVDD_GMII 1V05_DVDD_GMII 1V05_GMII 1V8 2V8 3V3 3V3_AVDD_GMII 3V3_DVDD_GMII 5V_STI VBUS_OTG VBUS_SW VDD VIN
net class NET-CLASS_50R_JTAG_JT: JTCK_SWCLK JTDI JTDO_TRACESWO JTMS_SWDIO
net class NET-CLASS_50R_TRACE-RGB_TRACED-LTDC: LTDC_B0 LTDC_B1 LTDC_B2 LTDC_B3 LTDC_B4 LTDC_B5 LTDC_B6 LTDC_B7 LTDC_DE LTDC_G0 LTDC_G1 LTDC_G2 LTDC_G3 LTDC_G4 LTDC_G5 LTDC_G6 LTDC_G7 LTDC_HSYNC LTDC_R0 LTDC_R1 LTDC_R2 LTDC_R3 LTDC_R4 LTDC_R5 LTDC_R6 LTDC_R7 LTDC_VSYNC TRACED0 TRACED1 TRACED2 TRACED3 TRACED4 TRACED5 TRACED6 TRACED7 TRACED8 TRACED9 TRACED10 TRACED11 TRACED12 TRACED13 TRACED14 TRACED15
net class NET-CLASS_50R_CLK: CAMERA_CLK ETH_CLK ETH_GTX_CLK ETH_RX_CLK JTCK_SWCLK LTDC_CLK MFX_SWCLK QSPI_CLK RXCLK SMARTCARD_CLK
net class NET-CLASS_50R_RGMII_ETH-RX: ETH_RX_DV ETH_RXD0 ETH_RXD1 ETH_RXD2 ETH_RXD3 NetR48_2 NetR51_2 NetR52_2 NetR55_2 RXDV_PHY_AD2
net class NET-CLASS_50R_RGMII_ETH-TX: ETH_TX_EN ETH_TXD0 ETH_TXD1 ETH_TXD2 ETH_TXD3
net class NET-CLASS_DIFF-100R_RJ45_D4: RJ45_D4_N RJ45_D4_P
net class NET-CLASS_DIFF-100R_RJ45_D3: RJ45_D3_N RJ45_D3_P
net class NET-CLASS_DIFF-100R_RJ45_D2: RJ45_D2_N RJ45_D2_P
net class NET-CLASS_DIFF-100R_RJ45_D1: RJ45_D1_N RJ45_D1_P
differential pair class DIFF-CLASS_DIFF-100R_RJ45_D4: RJ45_D4
differential pair class DIFF-CLASS_DIFF-100R_RJ45_D3: RJ45_D3
differential pair class DIFF-CLASS_DIFF-100R_RJ45_D2: RJ45_D2
differential pair class DIFF-CLASS_DIFF-100R_RJ45_D1: RJ45_D1
net class NET-CLASS_DIFF-90R_USB_DN4: USBDN4_N USBDN4_P
net class NET-CLASS_DIFF-90R_USB_DN3: USBDN3_N USBDN3_P
net class NET-CLASS_DIFF-90R_USB_DN2: USBDN2_N USBDN2_P
net class NET-CLASS_DIFF-90R_USB_DN1: USBDN1_N USBDN1_P
net class NET-CLASS_DIFF-90R_USB_AB: USB_AB_N USB_AB_P
net class NET-CLASS_DIFF-90R_USB4_CN26: USB4CN26_N USB4CN26_P
net class NET-CLASS_DIFF-90R_USB3_CN26: USB3CN26_N USB3CN26_P
net class NET-CLASS_DIFF-90R_USB2_CN25: USB2CN25_N USB2CN25_P
net class NET-CLASS_DIFF-90R_USB1_CN25: USB1CN25_N USB1CN25_P
differential pair class DIFF-CLASS_DIFF-90R_USB_AB: USB_AB
differential pair class DIFF-CLASS_DIFF-90R_USB4_CN26: USB4CN26
differential pair class DIFF-CLASS_DIFF-90R_USB3_CN26: USB3CN26
differential pair class DIFF-CLASS_DIFF-90R_USB2_CN25: USB2CN25
differential pair class DIFF-CLASS_DIFF-90R_USB1_CN25: USB1CN25
differential pair class DIFF-CLASS_DIFF-90R_USB_DN4: USBDN4
differential pair class DIFF-CLASS_DIFF-90R_USB_DN3: USBDN3
differential pair class DIFF-CLASS_DIFF-90R_USB_DN2: USBDN2
differential pair class DIFF-CLASS_DIFF-90R_USB_DN1: USBDN1
net class NET-CLASS_DIFF-100R_DSI_CK: DSI_CK_N DSI_CK_P
net class NET-CLASS_DIFF-100R_DSI_D0: DSI_D0_N DSI_D0_P
net class NET-CLASS_DIFF-100R_DSI_D1: DSI_D1_N DSI_D1_P
differential pair class DIFF-CLASS_DIFF-100R_DSI_CK: DSI_CK
differential pair class DIFF-CLASS_DIFF-100R_DSI_D0: DSI_D0
differential pair class DIFF-CLASS_DIFF-100R_DSI_D1: DSI_D1
differential pair class DIFF-CLASS_DIFF-90R_USB_CON: USB_CON
net class NET-CLASS_DIFF-90R_USB_CON: USB_CON_N USB_CON_P
differential pair class DIFF-CLASS_DIFF-90R_USB_HUB: USB_HUB
net class NET-CLASS_DIFF-90R_USB_HUB: USB_HUB_N USB_HUB_P
net class NET-CLASS_50R_DCMI: DCMI_D0 DCMI_D1 DCMI_D2 DCMI_D3 DCMI_D4 DCMI_D5 DCMI_D6 DCMI_D7 DCMI_D8 DCMI_D9 DCMI_D10 DCMI_D11 DCMI_HSYNC DCMI_PIXCK DCMI_VSYNC MC_EMERGENCYSTOP MC_ENA MC_ENB MC_ENINDEX MC_PFCPWM MC_PFCSYNC1 MC_PFCSYNC2 MC_VL MC_WL NetC118_2
net class NET-CLASS_NAND_D: NAND_D0 NAND_D1 NAND_D2 NAND_D3 NAND_D4 NAND_D5 NAND_D6 NAND_D7
net class NET-CLASS_NAND_X: NAND_ALE NAND_CLE NAND_NCE NAND_NOE NAND_NWAIT NAND_NWE
net class NET-CLASS_QSPI_BK1: QSPI_BK1_IO0 QSPI_BK1_IO1 QSPI_BK1_IO2 QSPI_BK1_IO3 QSPI_BK1_NCS
net class NET-CLASS_QSPI_BK2: QSPI_BK2_IO0 QSPI_BK2_IO1 QSPI_BK2_IO2 QSPI_BK2_IO3 QSPI_BK2_NCS
differential pair RJ45_D4: +RJ45_D4_P -RJ45_D4_N
differential pair RJ45_D3: +RJ45_D3_P -RJ45_D3_N
differential pair RJ45_D2: +RJ45_D2_P -RJ45_D2_N
differential pair RJ45_D1: +RJ45_D1_P -RJ45_D1_N
differential pair USBDN4: +USBDN4_P -USBDN4_N
differential pair USBDN3: +USBDN3_P -USBDN3_N
differential pair USBDN2: +USBDN2_P -USBDN2_N
differential pair USBDN1: +USBDN1_P -USBDN1_N
differential pair USB_AB: +USB_AB_P -USB_AB_N
differential pair USB4CN26: +USB4CN26_P -USB4CN26_N
differential pair USB3CN26: +USB3CN26_P -USB3CN26_N
differential pair USB2CN25: +USB2CN25_P -USB2CN25_N
differential pair USB1CN25: +USB1CN25_P -USB1CN25_N
differential pair DSI_D1: +DSI_D1_P -DSI_D1_N
differential pair DSI_D0: +DSI_D0_P -DSI_D0_N
differential pair DSI_CK: +DSI_CK_P -DSI_CK_N
differential pair USB_HUB: +USB_HUB_P -USB_HUB_N

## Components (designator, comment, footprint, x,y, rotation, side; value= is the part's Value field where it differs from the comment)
B1 ".designator" SWI_XIEJIA_MT-008A_6P 105,7.5 r45 top locked value=MT-008A
B2 ".designator" SWI_WEALTHMETAL_TD-0341_4P 79,7.5 r270 top locked value=SW-PUSH-CMS_BLACK
C1 ".designator" C0402 61.3,245.796 r270 top value=100nF
C2 ".designator" C0402 66.7,244.1 r0 top value=100nF
C3 ".designator" C0402 158.95,243.1 r0 top value=4.7uF
C4 ".designator" C0402 156.875,242.575 r90 top value=100nF
C5 ".designator" C0402 160.675,242.575 r90 top value=100nF
C6 ".designator" C0402 56.419,242.192 r90 top value=100nF
C7 ".designator" C0402 63.6,241.85 r90 top value=100nF
C8 ".designator" C0402 158.95,242.175 r0 top value=100nF
C9 ".designator" C0402 118,240.175 r270 top value=100nF
C10 ".designator" C0402 101,239.05 r270 top value=22nF
C11 ".designator" C0402 197.575,237.5 r180 top value=100nF
C12 ".designator" C0402 204.425,237.5 r180 top value=100nF
C13 ".designator" C0402 102.975,234.4 r90 top value=100nF
C14 ".designator" C0402 100.35,232.425 r270 top value=22nF
C15 ".designator" C0402 157.325,229.25 r0 top value=100nF
C16 ".designator" C0402 151.775,228.85 r270 top value=100nF
C17 ".designator" C0402 157.325,228.2 r180 top value=4.7uF
C18 ".designator" C0402 102.325,227.75 r90 top value=100nF
C19 ".designator" C0402 83.514,222.193 r90 top value=1uF
C20 ".designator" C0805 29.857,221.505 r0 top value=22uF
C21 ".designator" C0402 79.942,221.515 r90 top value=1uF
C22 ".designator" C0603 86.4,220.575 r90 top value=2.2uF
C23 ".designator" C0402 81.125,220.575 r270 top value=4.7uF
C24 ".designator" C0402 82.05,220.575 r270 top value=4.7uF
C25 ".designator" C0402 84.85,220.575 r270 top value=100nF
C26 ".designator" C0603 88.375,220.375 r0 top value=2.2uF
C27 ".designator" C0402 83.45,219.85 r0 top value=100nF
C28 ".designator" C0603 88.373,218.996 r0 top value=2.2uF
C29 ".designator" C0402 204.391,218.518 r0 top value=100nF
C30 ".designator" C0402 197.575,218.5 r180 top value=100nF
C31 ".designator" C0402 79.575,218.45 r0 top value=4.7uF
C32 ".designator" C0805 28.859,216.997 r90 top value=22uF
C33 ".designator" C0402 30.73,217.111 r90 top value=100nF
C34 ".designator" C0402 88.05,217.475 r180 top value=100nF
C35 ".designator" C0402 79.575,216.475 r0 top value=4.7uF
C36 ".designator" C0402 88.05,216.425 r180 top value=100nF
C37 ".designator" C0805 28.252,213.971 r180 top value=22uF
C38 ".designator" C0402 77.904,214.238 r0 top value=4.7uF
C39 ".designator" C0402 77.904,213.313 r0 top value=4.7uF
C40 ".designator" C0402 83.2,212.9 r0 top value=100nF
C41 ".designator" C0402 79.595,212.093 r90 top value=4.7uF
C42 ".designator" C0402 80.595,212.093 r90 top value=1uF
C43 ".designator" C0402 81.595,212.093 r90 top value=100nF
C44 ".designator" C0402 84.65,211.975 r90 top value=1uF
C45 ".designator" C0402 28.533,211.573 r270 top value=10pF
C46 ".designator" C0402 28.533,209.873 r90 top value=10pF
C47 ".designator" C0805 38.588,206.407 r270 top value=22uF
C48 ".designator" C0805 35.342,205.145 r270 top value=22uF
C49 ".designator" C0402 33.598,202.473 r90 top value=100nF
C50 ".designator" C0402 24.421,202.195 r90 top value=100nF
C51 ".designator" C0805 25.791,201.589 r90 top value=22uF
C52 ".designator" CPOL_TAJ-A_1206_H180 192.6,176 r90 top value=10uF
C53 ".designator" C0402 194.6,176 r270 top value=100nF
C54 ".designator" C0402 192.15,173.175 r0 top value=10nF
C55 ".designator" C0402 97.777,170.589 r0 top value=100nF
C56 ".designator" C0402 93.456,164.717 r90 top value=100nF
C57 ".designator" C0402 104.95,163.95 r180 top value=100nF
C58 ".designator" C0402 104.952,161.95 r180 top value=100nF
C59 ".designator" C0402 123.262,160.958 r270 top value=10nF
C60 ".designator" C0402 144.925,156.62 r180 top value=100pF
C61 ".designator" C0402 24.832,155.973 r0 top value=100nF
C62 ".designator" C0402 17.725,153.6 r90 top value=100nF
C63 ".designator" C0402 28.838,152.652 r270 top value=100nF
C64 ".designator" C0402 17.325,152.275 r0 top value=100nF
C65 ".designator" C0402 28.481,150.348 r90 top value=100nF
C66 ".designator" C0402 72.538,130.787 r90 top value=100nF
C67 ".designator" C0402 88.4,127.825 r180 top value=100nF
C68 ".designator" C0402 86.5,126.7 r0 top value=10nF
C69 ".designator" CPOL_TAJ-A_1206_H180 7.279,119.18 r270 top value=4.7uF
C70 ".designator" C0402 175.325,115.25 r0 top value=100nF
C71 ".designator" C0402 77.999,114.409 r0 top value=100nF
C72 ".designator" C0402 76,113.5 r0 top value=100nF
C73 ".designator" C0402 181.75,112.35 r0 top value=100nF
C74 ".designator" C0402 80,111.7 r180 top value=100nF
C75 ".designator" C0402 74.725,111.3 r0 top value=100nF
C76 ".designator" CPOL_TAJ-C_2312_H2P6 21.17,108.031 r90 top value=220uF
C77 ".designator" C0805 53.458,109 r270 top value=47uF
C78 ".designator" C0402 51.041,109.007 r270 top value=100nF
C79 ".designator" C0402 86.7,108.6 r270 top value=1uF
C80 ".designator" C0402 31.634,108.414 r0 top value=18pF
C81 ".designator" C0402 33.429,108.414 r180 top value=18pF
C82 ".designator" C0402 84.9,107.325 r270 top value=100nF
C83 ".designator" C0402 30.904,106.346 r270 top value=100nF
C84 ".designator" C0402 34.735,106.312 r270 top value=100nF
C85 ".designator" C0402 37.825,106.35 r180 top value=10nF
C86 ".designator" C0402 83.8,105.4 r90 top value=10nF
C87 ".designator" C0402 21.595,103.931 r180 top value=100nF
C88 ".designator" C0402 71.425,102.425 r90 top value=100nF
C89 ".designator" C0402 72.375,102.425 r90 top value=100nF
C90 ".designator" C0402 83.837,101.76 r90 top value=100nF
C91 ".designator" C0402 81.27,99.374 r90 top value=100nF
C92 ".designator" C0402 73.25,98.378 r0 top value=100nF
C93 ".designator" C0402 75.272,97.464 r0 top value=100nF
C94 ".designator" C0402 31.058,97.399 r180 top value=100nF
C95 ".designator" C0402 32.825,96.985 r90 top value=100nF
C96 ".designator" C0402 33.725,96.985 r90 top value=100nF
C97 ".designator" C0402 34.65,96.985 r90 top value=4.7uF
C98 ".designator" CPOL_TAJ-A_1206_H180 120.225,95.075 r180 top value=10uF
C99 ".designator" C0402 21.625,95.571 r180 top value=100nF
C100 ".designator" CPOL_TAJ-C_2312_H2P6 21.17,91.466 r270 top value=220uF
C101 ".designator" C0402 120.225,93.075 r0 top value=100nF
C102 ".designator" CPOL_TAJ-C_2312_H2P6 21.17,84.295 r90 top value=220uF
C103 ".designator" C0402 111.75,82.5 r90 top value=100nF
C104 ".designator" C0402 117.8,82.5 r90 top value=100nF
C105 ".designator" C0402 21.613,80.219 r180 top value=100nF
C106 ".designator" C0402 21.569,71.435 r180 top value=100nF
C107 ".designator" CPOL_TAJ-C_2312_H2P6 21.17,67.312 r270 top value=220uF
C108 ".designator" C0402 177.368,52.8 r180 top value=100pF
C109 ".designator" C0402 177.368,51.525 r0 top value=100pF
C110 ".designator" C0402 177.368,48.975 r0 top value=100pF
C111 ".designator" C0402 177.368,46.45 r0 top value=100pF
C112 ".designator" C0402 177.368,43.9 r0 top value=100pF
C113 ".designator" C0402 175.927,42.221 r90 top value=100nF
C114 ".designator" C0402 175.927,36.83 r270 top value=100pF
C115 ".designator" C0402 175.927,34.215 r270 top value=100pF
C116 ".designator" C0402 175.927,31.651 r270 top value=100pF
C117 ".designator" C0402 175.927,27.844 r270 top value=100nF
C118 ".designator" C0402 175.747,13.835 r270 top value=1nF
C119 ".designator" C0402 83.75,11.875 r270 top value=100nF
C120 ".designator" C0402 20.646,231.316 r90 bottom value=100nF
C121 ".designator" C0402 86.45,220.925 r270 bottom value=100nF
C122 ".designator" C0402 21.425,212.982 r270 bottom value=100nF
C123 "C121" C0402 19.925,212.982 r270 bottom value=100nF
C124 ".designator" C0402 18.425,212.982 r270 bottom value=100nF
C125 ".designator" C0402 24.756,212.028 r0 bottom value=100nF
C126 ".designator" C0402 23.685,210.794 r0 bottom value=100nF
C127 ".designator" C0402 16.675,210.525 r180 bottom value=100nF
C128 ".designator" C0402 24.785,208.978 r0 bottom value=100nF
C129 ".designator" C0402 16.675,207.525 r180 bottom value=100nF
C130 ".designator" C0402 18.935,204.181 r270 bottom value=100nF
C131 ".designator" C0402 24.605,204.023 r0 bottom value=100nF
